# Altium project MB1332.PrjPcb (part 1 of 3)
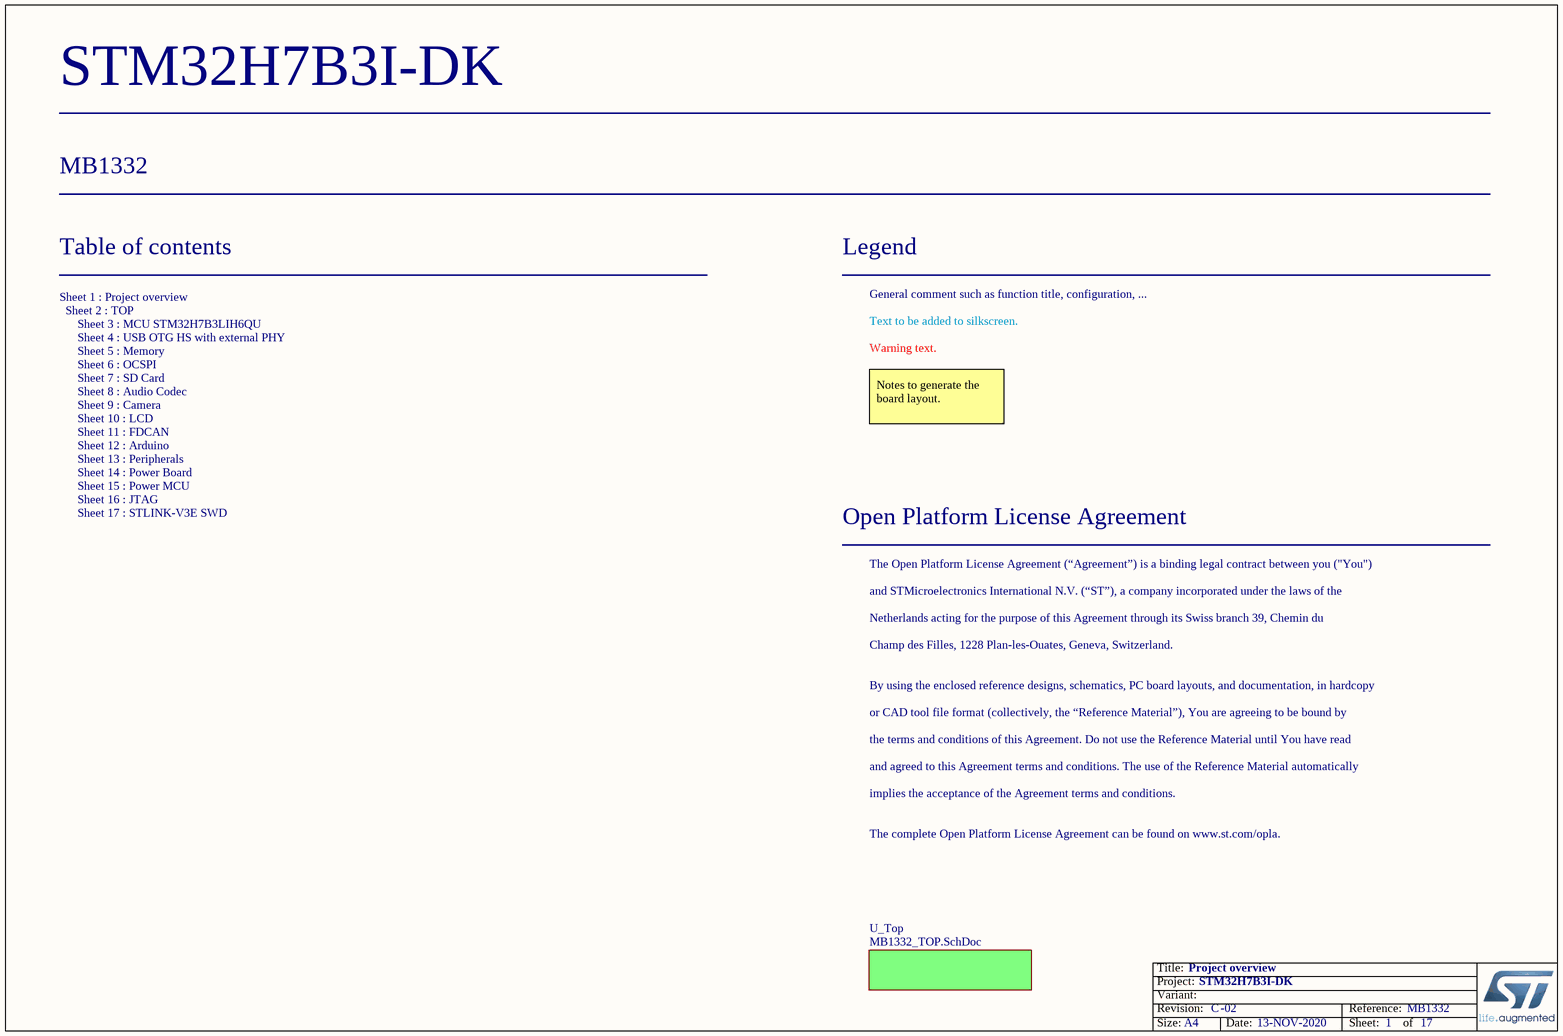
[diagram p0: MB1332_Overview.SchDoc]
Board_Reference: MB1332; Board_PCB_Revision: C; Board_Name: STM32H7B3I-DK; Board_Document_Date: 13-NOV-2020; Board_Assembly_Revision: 02
17 sheets, 382 parts. Net scope: flat (ports and power ports of the same name join across sheets).
Board file: MB1332.PcbDoc
Sheets:
  MB1332_Overview.SchDoc
    U_Top = MB1332_TOP.SchDoc
      U_Audio_Codec = Audio_Codec.SchDoc
      U_Camera = Camera.SchDoc
      U_FDCAN = FDCAN.SchDoc
      U_LCD = LCD.SchDoc
      U_Memory = Memory.SchDoc
      U_OCSPI = OCSPI.SchDoc
      U_Peripherals = Peripherals.SchDoc
      U_SDcard = SDcard.SchDoc
      U_USB_OTG_HS_externalPHY = USB_OTG_HS_externalPHY.SchDoc
      U_MCU = MCU.SchDoc
      U_Arduino = Arduino.SchDoc
      U_JTAG = JTAG.SchDoc
      U_STLink_V3E_SWD = STLink_V3E_SWD.SchDoc
      U_Power_Board = Power_Board.SchDoc
      U_Power_MCU = Power_MCU.SchDoc

## Sheet MB1332_Overview.SchDoc: Project overview
size A4; Date: Not used; ApprovedBy: Not used; CheckedBy: Not used; Author: Not used; CompanyName: STMicroelectronics; DrawnBy: Not used; Engineer: Not used; Organization: Not used; Address1: Not used; Address2: Not used; Address3: Not used; Address4: Not used; DocumentNumber: Not used; Revision: Not used; SheetNumber: 1; SheetTotal: 17

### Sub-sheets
U_Top = MB1332_TOP.SchDoc: no entries

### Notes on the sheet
- Table of contents
- Legend
- General comment such as function title, configuration, ...
- Text to be added to silkscreen.
- Warning text.
- Notes to generate the board layout.
- Sheet 1 : Project overview
  Sheet 2 : TOP
  Sheet 3 : MCU STM32H7B3LIH6QU
  Sheet 4 : USB OTG HS with external PHY
  Sheet 5 : Memory
  Sheet 6 : OCSPI
  Sheet 7 : SD Card
  Sheet 8 : Audio Codec
  Sheet 9 : Camera
  Sheet 10 : LCD
  Sheet 11 : FDCAN
  Sheet 12 : Arduino
  Sheet 13 : Peripherals
  Sheet 14 : Power Board
  Sheet 15 : Power MCU
  Sheet 16 : JTAG
  Sheet 17 : STLINK-V3E SWD
- Open Platform License Agreement
- The Open Platform License Agreement (“Agreement”) is a binding legal contract between you ("You")
- and STMicroelectronics International N.V. (“ST”), a company incorporated under the laws of the
- Netherlands acting for the purpose of this Agreement through its Swiss branch 39, Chemin du
- Champ des Filles, 1228 Plan-les-Ouates, Geneva, Switzerland.
- By using the enclosed reference designs, schematics, PC board layouts, and documentation, in hardcopy
- or CAD tool file format (collectively, the “Reference Material”), You are agreeing to be bound by
- the terms and conditions of this Agreement. Do not use the Reference Material until You have read
- and agreed to this Agreement terms and conditions. The use of the Reference Material automatically
- implies the acceptance of the Agreement terms and conditions.
- The complete Open Platform License Agreement can be found on www.st.com/opla.

## Sheet MB1332_TOP.SchDoc: TOP
size A3; Date: Not used; ApprovedBy: Not used; CheckedBy: Not used; Author: Not used; CompanyName: STMicroelectronics; DrawnBy: Not used; Engineer: Not used; Organization: Not used; Address1: Not used; Address2: Not used; Address3: Not used; Address4: Not used; DocumentNumber: Not used; Revision: Not used; SheetNumber: 2; SheetTotal: 17
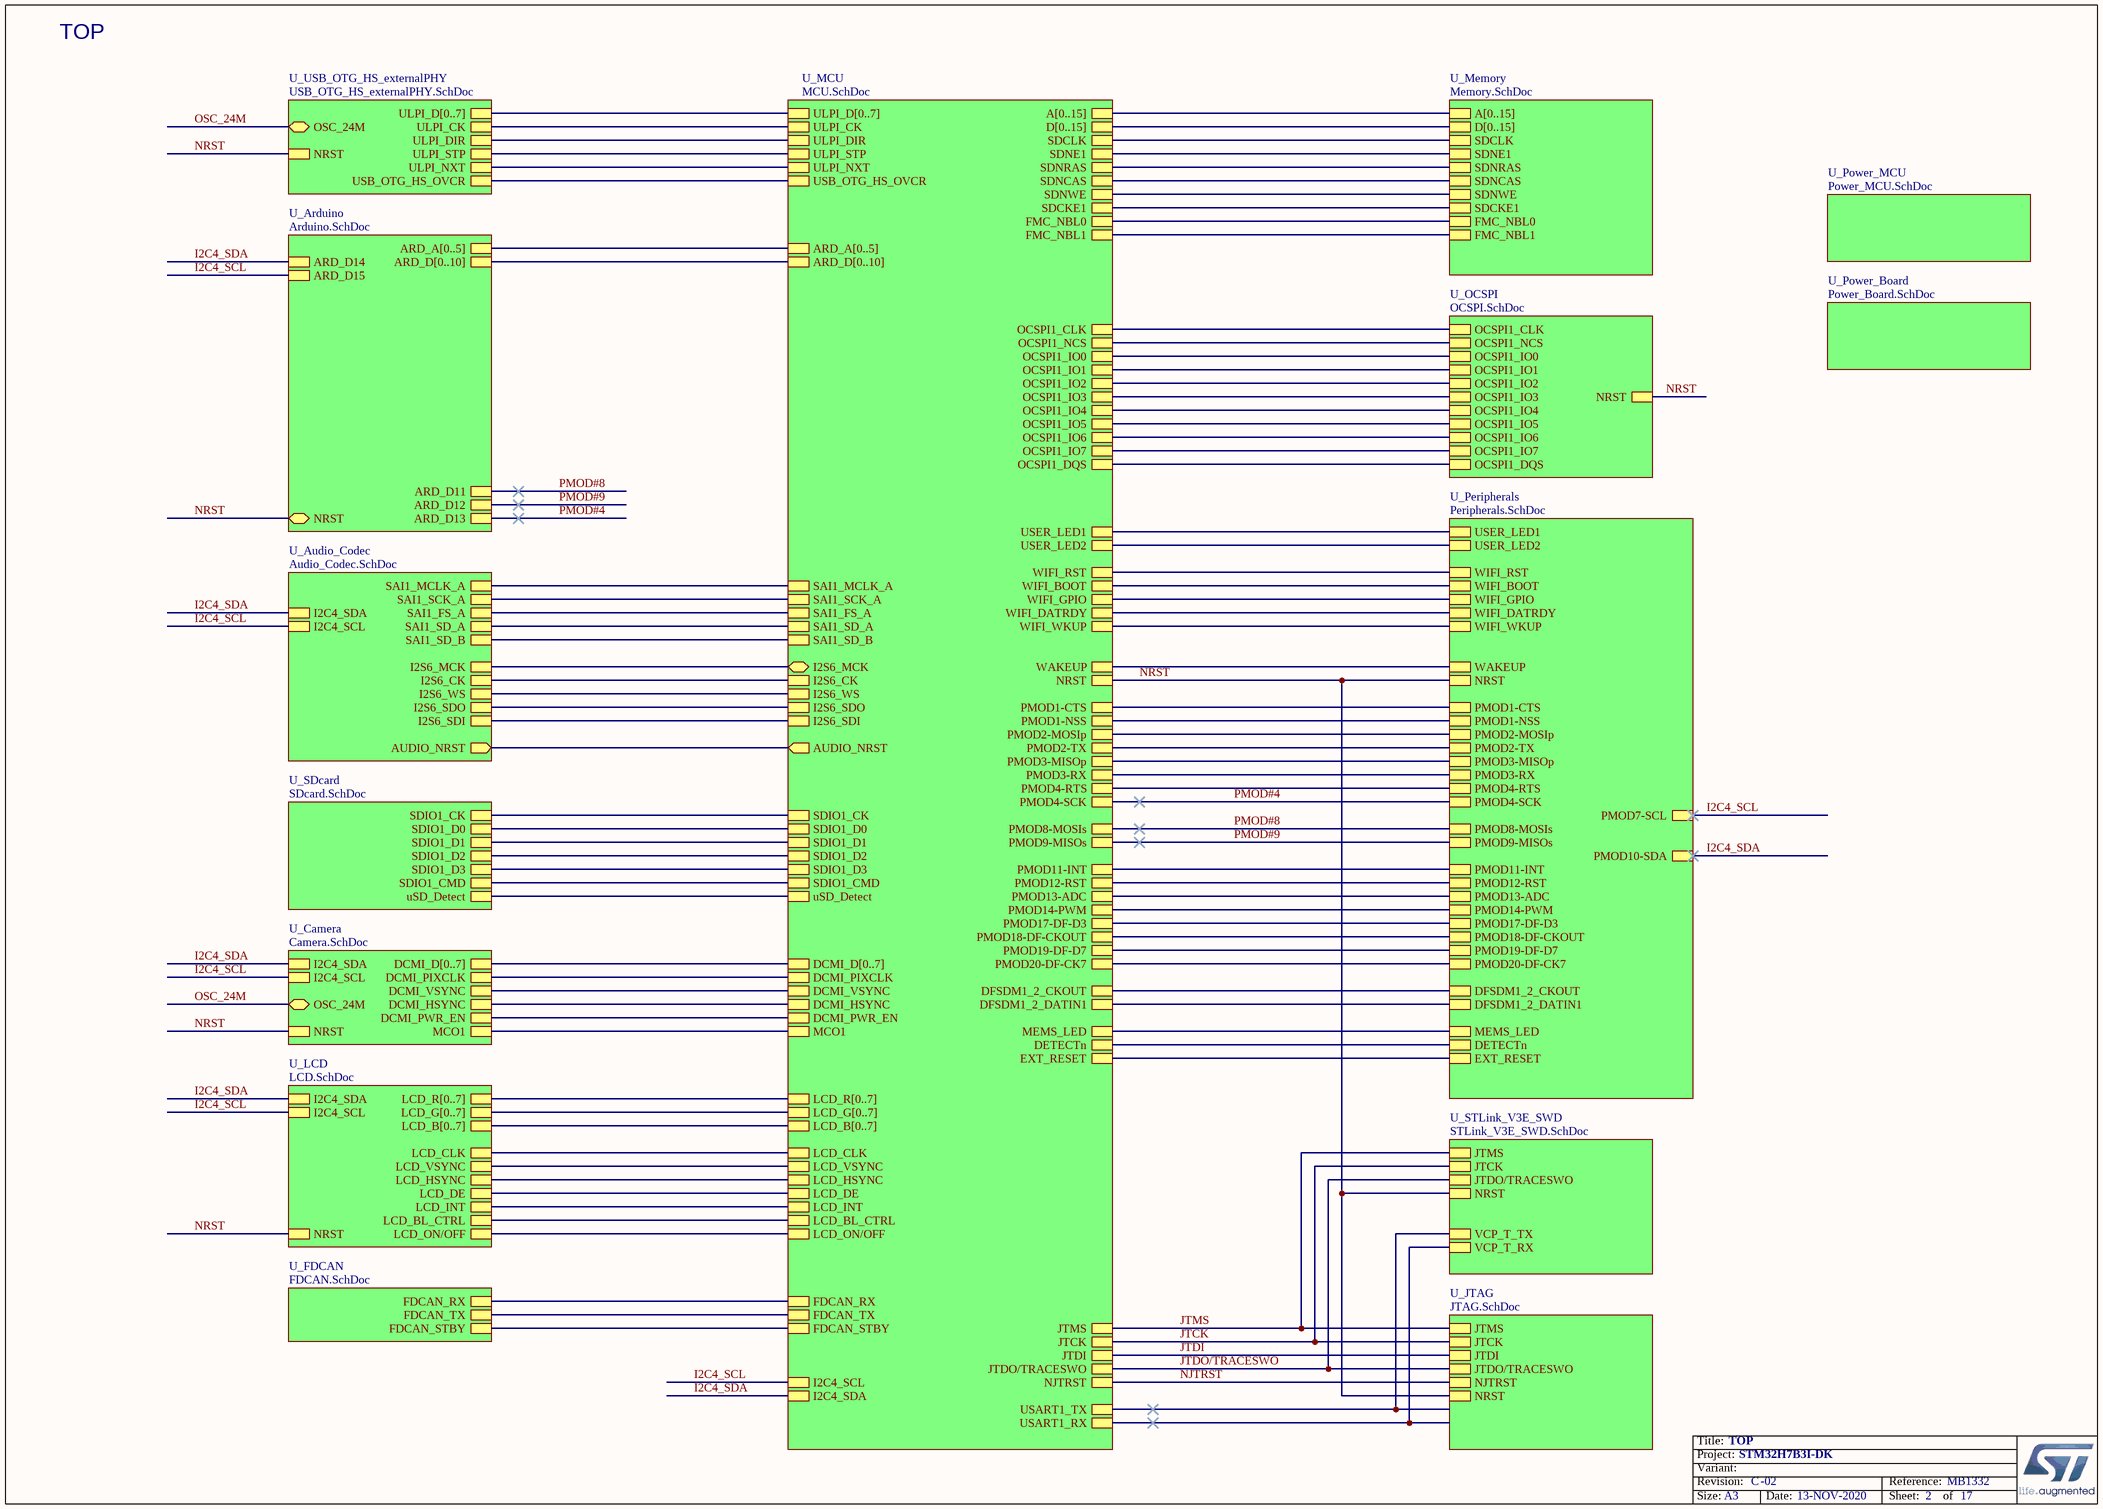
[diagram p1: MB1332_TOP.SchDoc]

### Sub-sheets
U_Arduino = Arduino.SchDoc: ARD_D13, ARD_D12, ARD_D11, ARD_D15, ARD_D14, ARD_A[0..5], ARD_D[0..10], NRST (bidir)
U_Audio_Codec = Audio_Codec.SchDoc: SAI1_MCLK_A, SAI1_SCK_A, SAI1_FS_A, SAI1_SD_A, SAI1_SD_B, I2C4_SCL, I2C4_SDA, I2S6_MCK, I2S6_CK, I2S6_WS, I2S6_SDO, I2S6_SDI, AUDIO_NRST (out)
U_Camera = Camera.SchDoc: NRST, DCMI_D[0..7], DCMI_PWR_EN, DCMI_VSYNC, DCMI_PIXCLK, I2C4_SDA, I2C4_SCL, DCMI_HSYNC, MCO1, OSC_24M
U_FDCAN = FDCAN.SchDoc: FDCAN_STBY, FDCAN_RX, FDCAN_TX
U_JTAG = JTAG.SchDoc: JTMS, JTCK, JTDI, JTDO/TRACESWO, NJTRST, NRST
U_LCD = LCD.SchDoc: LCD_R[0..7], I2C4_SDA, I2C4_SCL, LCD_B[0..7], LCD_G[0..7], NRST, LCD_HSYNC, LCD_VSYNC, LCD_CLK, LCD_DE, LCD_INT, LCD_BL_CTRL, LCD_ON/OFF
U_MCU = MCU.SchDoc: OCSPI1_NCS, SAI1_MCLK_A, SDNCAS, SDNE1, SDCKE1, NRST, LCD_HSYNC, LCD_VSYNC, LCD_CLK, MCO1, OCSPI1_CLK, OCSPI1_DQS, SDIO1_D0, SDIO1_D1, SDIO1_D2, SDIO1_D3, SDIO1_CK, WAKEUP, SDIO1_CMD, FMC_NBL0, FMC_NBL1, SDNRAS, LCD_G[0..7], LCD_B[0..7], D[0..15], A[0..15], ULPI_D[0..7], LCD_R[0..7], LCD_DE, ULPI_STP, ULPI_CK, LCD_INT, uSD_Detect, LCD_BL_CTRL, SAI1_SD_B, SAI1_FS_A, SAI1_SCK_A, SAI1_SD_A, JTMS, JTCK, JTDI, JTDO/TRACESWO, NJTRST, DCMI_HSYNC, DCMI_D[0..7], DCMI_PIXCLK, OCSPI1_IO1, OCSPI1_IO2, OCSPI1_IO3, OCSPI1_IO4, OCSPI1_IO7, OCSPI1_IO6, OCSPI1_IO5, ULPI_DIR, ULPI_NXT, SDNWE, DCMI_VSYNC, DCMI_PWR_EN, I2C4_SDA, I2C4_SCL, I2S6_SDO, I2S6_SDI, I2S6_CK, SDCLK, USB_OTG_HS_OVCR, USART1_TX, USART1_RX, OCSPI1_IO0, LCD_ON/OFF, FDCAN_RX, FDCAN_TX, FDCAN_STBY, MEMS_LED, EXT_RESET, DFSDM1_2_CKOUT, DFSDM1_2_DATIN1, I2S6_WS, WIFI_RST, ARD_A[0..5], ARD_D[0..10], USER_LED2, USER_LED1, AUDIO_NRST (out), PMOD13-ADC, PMOD12-RST, PMOD4-SCK, PMOD20-DF-CK7, PMOD8-MOSIs, PMOD2-MOSIp, PMOD3-RX, PMOD1-NSS, PMOD1-CTS, PMOD2-TX, PMOD11-INT, PMOD4-RTS, PMOD14-PWM, PMOD18-DF-CKOUT, PMOD9-MISOs, PMOD17-DF-D3, PMOD19-DF-D7, PMOD3-MISOp, WIFI_BOOT, I2S6_MCK (bidir), WIFI_WKUP, WIFI_GPIO, WIFI_DATRDY, DETECTn
U_Memory = Memory.SchDoc: FMC_NBL0, FMC_NBL1, D[0..15], A[0..15], SDNCAS, SDNWE, SDNRAS, SDNE1, SDCKE1, SDCLK
U_OCSPI = OCSPI.SchDoc: NRST, OCSPI1_IO0, OCSPI1_IO1, OCSPI1_IO2, OCSPI1_IO3, OCSPI1_IO4, OCSPI1_IO5, OCSPI1_IO6, OCSPI1_IO7, OCSPI1_DQS, OCSPI1_CLK, OCSPI1_NCS
U_Peripherals = Peripherals.SchDoc: WIFI_RST, WAKEUP, NRST, DFSDM1_2_CKOUT, DFSDM1_2_DATIN1, MEMS_LED, EXT_RESET, USER_LED2, USER_LED1, PMOD4-RTS, PMOD2-MOSIp, PMOD3-MISOp, PMOD1-CTS, PMOD2-TX, PMOD8-MOSIs, PMOD9-MISOs, PMOD3-RX, PMOD4-SCK, PMOD7-SCL, PMOD10-SDA, PMOD11-INT, PMOD12-RST, PMOD17-DF-D3, PMOD18-DF-CKOUT, PMOD19-DF-D7, PMOD13-ADC, PMOD14-PWM, PMOD20-DF-CK7, PMOD1-NSS, WIFI_BOOT, WIFI_WKUP, WIFI_GPIO, WIFI_DATRDY, DETECTn
U_Power_Board = Power_Board.SchDoc: no entries
U_Power_MCU = Power_MCU.SchDoc: no entries
U_SDcard = SDcard.SchDoc: SDIO1_D0, SDIO1_D1, SDIO1_D2, SDIO1_D3, SDIO1_CMD, SDIO1_CK, uSD_Detect
U_STLink_V3E_SWD = STLink_V3E_SWD.SchDoc: JTCK, JTDO/TRACESWO, NRST, JTMS, VCP_T_TX, VCP_T_RX
U_USB_OTG_HS_externalPHY = USB_OTG_HS_externalPHY.SchDoc: ULPI_D[0..7], ULPI_CK, ULPI_DIR, ULPI_NXT, ULPI_STP, NRST, USB_OTG_HS_OVCR, OSC_24M

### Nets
I2C4_SCL: sheet U_Audio_Codec/I2C4_SCL, sheet U_Camera/I2C4_SCL, sheet U_LCD/I2C4_SCL, sheet U_Peripherals/PMOD7-SCL, sheet U_MCU/I2C4_SCL, sheet U_Arduino/ARD_D15
I2C4_SDA: sheet U_Audio_Codec/I2C4_SDA, sheet U_Camera/I2C4_SDA, sheet U_LCD/I2C4_SDA, sheet U_Peripherals/PMOD10-SDA, sheet U_MCU/I2C4_SDA, sheet U_Arduino/ARD_D14
JTCK: sheet U_MCU/JTCK, sheet U_JTAG/JTCK, sheet U_STLink_V3E_SWD/JTCK
JTDI: sheet U_MCU/JTDI, sheet U_JTAG/JTDI
JTDO/TRACESWO: sheet U_MCU/JTDO/TRACESWO, sheet U_JTAG/JTDO/TRACESWO, sheet U_STLink_V3E_SWD/JTDO/TRACESWO
JTMS: sheet U_MCU/JTMS, sheet U_JTAG/JTMS, sheet U_STLink_V3E_SWD/JTMS
NJTRST: sheet U_MCU/NJTRST, sheet U_JTAG/NJTRST
NRST: sheet U_Camera/NRST, sheet U_LCD/NRST, sheet U_OCSPI/NRST, sheet U_Peripherals/NRST, sheet U_USB_OTG_HS_externalPHY/NRST, sheet U_MCU/NRST, sheet U_Arduino/NRST, sheet U_JTAG/NRST, sheet U_STLink_V3E_SWD/NRST
OSC_24M: sheet U_Camera/OSC_24M, sheet U_USB_OTG_HS_externalPHY/OSC_24M
PMOD#4: sheet U_Peripherals/PMOD4-SCK, sheet U_MCU/PMOD4-SCK, sheet U_Arduino/ARD_D13
PMOD#8: sheet U_Peripherals/PMOD8-MOSIs, sheet U_MCU/PMOD8-MOSIs, sheet U_Arduino/ARD_D11
PMOD#9: sheet U_Peripherals/PMOD9-MISOs, sheet U_MCU/PMOD9-MISOs, sheet U_Arduino/ARD_D12
(unnamed): sheet U_Audio_Codec/SAI1_MCLK_A, sheet U_MCU/SAI1_MCLK_A
(unnamed): sheet U_Audio_Codec/SAI1_SCK_A, sheet U_MCU/SAI1_SCK_A  [a separate net that carries the same name]
(unnamed): sheet U_Audio_Codec/SAI1_FS_A, sheet U_MCU/SAI1_FS_A  [a separate net that carries the same name]
(unnamed): sheet U_Audio_Codec/SAI1_SD_A, sheet U_MCU/SAI1_SD_A  [a separate net that carries the same name]
(unnamed): sheet U_Audio_Codec/SAI1_SD_B, sheet U_MCU/SAI1_SD_B  [a separate net that carries the same name]
(unnamed): sheet U_Audio_Codec/I2S6_MCK, sheet U_MCU/I2S6_MCK  [a separate net that carries the same name]
(unnamed): sheet U_Audio_Codec/I2S6_CK, sheet U_MCU/I2S6_CK  [a separate net that carries the same name]
(unnamed): sheet U_Audio_Codec/I2S6_WS, sheet U_MCU/I2S6_WS  [a separate net that carries the same name]
(unnamed): sheet U_Audio_Codec/I2S6_SDO, sheet U_MCU/I2S6_SDO  [a separate net that carries the same name]
(unnamed): sheet U_Audio_Codec/I2S6_SDI, sheet U_MCU/I2S6_SDI  [a separate net that carries the same name]
(unnamed): sheet U_Audio_Codec/AUDIO_NRST, sheet U_MCU/AUDIO_NRST  [a separate net that carries the same name]
(unnamed): sheet U_Camera/DCMI_PWR_EN, sheet U_MCU/DCMI_PWR_EN  [a separate net that carries the same name]
(unnamed): sheet U_Camera/DCMI_VSYNC, sheet U_MCU/DCMI_VSYNC  [a separate net that carries the same name]
(unnamed): sheet U_Camera/DCMI_PIXCLK, sheet U_MCU/DCMI_PIXCLK  [a separate net that carries the same name]
(unnamed): sheet U_Camera/DCMI_HSYNC, sheet U_MCU/DCMI_HSYNC  [a separate net that carries the same name]
(unnamed): sheet U_Camera/MCO1, sheet U_MCU/MCO1  [a separate net that carries the same name]
(unnamed): sheet U_FDCAN/FDCAN_STBY, sheet U_MCU/FDCAN_STBY  [a separate net that carries the same name]
(unnamed): sheet U_FDCAN/FDCAN_RX, sheet U_MCU/FDCAN_RX  [a separate net that carries the same name]
(unnamed): sheet U_FDCAN/FDCAN_TX, sheet U_MCU/FDCAN_TX  [a separate net that carries the same name]
(unnamed): sheet U_LCD/LCD_HSYNC, sheet U_MCU/LCD_HSYNC  [a separate net that carries the same name]
(unnamed): sheet U_LCD/LCD_VSYNC, sheet U_MCU/LCD_VSYNC  [a separate net that carries the same name]
(unnamed): sheet U_LCD/LCD_CLK, sheet U_MCU/LCD_CLK  [a separate net that carries the same name]
(unnamed): sheet U_LCD/LCD_DE, sheet U_MCU/LCD_DE  [a separate net that carries the same name]
(unnamed): sheet U_LCD/LCD_INT, sheet U_MCU/LCD_INT  [a separate net that carries the same name]
(unnamed): sheet U_LCD/LCD_BL_CTRL, sheet U_MCU/LCD_BL_CTRL  [a separate net that carries the same name]
(unnamed): sheet U_LCD/LCD_ON/OFF, sheet U_MCU/LCD_ON/OFF  [a separate net that carries the same name]
(unnamed): sheet U_Memory/FMC_NBL0, sheet U_MCU/FMC_NBL0  [a separate net that carries the same name]
(unnamed): sheet U_Memory/FMC_NBL1, sheet U_MCU/FMC_NBL1  [a separate net that carries the same name]
(unnamed): sheet U_Memory/SDNCAS, sheet U_MCU/SDNCAS  [a separate net that carries the same name]
(unnamed): sheet U_Memory/SDNWE, sheet U_MCU/SDNWE  [a separate net that carries the same name]
(unnamed): sheet U_Memory/SDNRAS, sheet U_MCU/SDNRAS  [a separate net that carries the same name]
(unnamed): sheet U_Memory/SDNE1, sheet U_MCU/SDNE1  [a separate net that carries the same name]
(unnamed): sheet U_Memory/SDCKE1, sheet U_MCU/SDCKE1  [a separate net that carries the same name]
(unnamed): sheet U_Memory/SDCLK, sheet U_MCU/SDCLK  [a separate net that carries the same name]
(unnamed): sheet U_OCSPI/OCSPI1_IO0, sheet U_MCU/OCSPI1_IO0  [a separate net that carries the same name]
(unnamed): sheet U_OCSPI/OCSPI1_IO1, sheet U_MCU/OCSPI1_IO1  [a separate net that carries the same name]
(unnamed): sheet U_OCSPI/OCSPI1_IO2, sheet U_MCU/OCSPI1_IO2  [a separate net that carries the same name]
(unnamed): sheet U_OCSPI/OCSPI1_IO3, sheet U_MCU/OCSPI1_IO3  [a separate net that carries the same name]
(unnamed): sheet U_OCSPI/OCSPI1_IO4, sheet U_MCU/OCSPI1_IO4  [a separate net that carries the same name]
(unnamed): sheet U_OCSPI/OCSPI1_IO5, sheet U_MCU/OCSPI1_IO5  [a separate net that carries the same name]
(unnamed): sheet U_OCSPI/OCSPI1_IO6, sheet U_MCU/OCSPI1_IO6  [a separate net that carries the same name]
(unnamed): sheet U_OCSPI/OCSPI1_IO7, sheet U_MCU/OCSPI1_IO7  [a separate net that carries the same name]
(unnamed): sheet U_OCSPI/OCSPI1_DQS, sheet U_MCU/OCSPI1_DQS  [a separate net that carries the same name]
(unnamed): sheet U_OCSPI/OCSPI1_CLK, sheet U_MCU/OCSPI1_CLK  [a separate net that carries the same name]
(unnamed): sheet U_OCSPI/OCSPI1_NCS, sheet U_MCU/OCSPI1_NCS  [a separate net that carries the same name]
(unnamed): sheet U_Peripherals/WIFI_RST, sheet U_MCU/WIFI_RST  [a separate net that carries the same name]
(unnamed): sheet U_Peripherals/WAKEUP, sheet U_MCU/WAKEUP  [a separate net that carries the same name]
(unnamed): sheet U_Peripherals/DFSDM1_2_CKOUT, sheet U_MCU/DFSDM1_2_CKOUT  [a separate net that carries the same name]
(unnamed): sheet U_Peripherals/DFSDM1_2_DATIN1, sheet U_MCU/DFSDM1_2_DATIN1  [a separate net that carries the same name]
(unnamed): sheet U_Peripherals/MEMS_LED, sheet U_MCU/MEMS_LED  [a separate net that carries the same name]
(unnamed): sheet U_Peripherals/EXT_RESET, sheet U_MCU/EXT_RESET  [a separate net that carries the same name]
(unnamed): sheet U_Peripherals/USER_LED2, sheet U_MCU/USER_LED2  [a separate net that carries the same name]
(unnamed): sheet U_Peripherals/USER_LED1, sheet U_MCU/USER_LED1  [a separate net that carries the same name]
(unnamed): sheet U_Peripherals/PMOD4-RTS, sheet U_MCU/PMOD4-RTS  [a separate net that carries the same name]
(unnamed): sheet U_Peripherals/PMOD2-MOSIp, sheet U_MCU/PMOD2-MOSIp  [a separate net that carries the same name]
(unnamed): sheet U_Peripherals/PMOD3-MISOp, sheet U_MCU/PMOD3-MISOp  [a separate net that carries the same name]
(unnamed): sheet U_Peripherals/PMOD1-CTS, sheet U_MCU/PMOD1-CTS  [a separate net that carries the same name]
(unnamed): sheet U_Peripherals/PMOD2-TX, sheet U_MCU/PMOD2-TX  [a separate net that carries the same name]
(unnamed): sheet U_Peripherals/PMOD3-RX, sheet U_MCU/PMOD3-RX  [a separate net that carries the same name]
(unnamed): sheet U_Peripherals/PMOD11-INT, sheet U_MCU/PMOD11-INT  [a separate net that carries the same name]
(unnamed): sheet U_Peripherals/PMOD12-RST, sheet U_MCU/PMOD12-RST  [a separate net that carries the same name]
(unnamed): sheet U_Peripherals/PMOD17-DF-D3, sheet U_MCU/PMOD17-DF-D3  [a separate net that carries the same name]
(unnamed): sheet U_Peripherals/PMOD18-DF-CKOUT, sheet U_MCU/PMOD18-DF-CKOUT  [a separate net that carries the same name]
(unnamed): sheet U_Peripherals/PMOD19-DF-D7, sheet U_MCU/PMOD19-DF-D7  [a separate net that carries the same name]
(unnamed): sheet U_Peripherals/PMOD13-ADC, sheet U_MCU/PMOD13-ADC  [a separate net that carries the same name]
(unnamed): sheet U_Peripherals/PMOD14-PWM, sheet U_MCU/PMOD14-PWM  [a separate net that carries the same name]
(unnamed): sheet U_Peripherals/PMOD20-DF-CK7, sheet U_MCU/PMOD20-DF-CK7  [a separate net that carries the same name]
(unnamed): sheet U_Peripherals/PMOD1-NSS, sheet U_MCU/PMOD1-NSS  [a separate net that carries the same name]
(unnamed): sheet U_Peripherals/WIFI_BOOT, sheet U_MCU/WIFI_BOOT  [a separate net that carries the same name]
(unnamed): sheet U_Peripherals/WIFI_WKUP, sheet U_MCU/WIFI_WKUP  [a separate net that carries the same name]
(unnamed): sheet U_Peripherals/WIFI_GPIO, sheet U_MCU/WIFI_GPIO  [a separate net that carries the same name]
(unnamed): sheet U_Peripherals/WIFI_DATRDY, sheet U_MCU/WIFI_DATRDY  [a separate net that carries the same name]
(unnamed): sheet U_Peripherals/DETECTn, sheet U_MCU/DETECTn  [a separate net that carries the same name]
(unnamed): sheet U_SDcard/SDIO1_D0, sheet U_MCU/SDIO1_D0  [a separate net that carries the same name]
(unnamed): sheet U_SDcard/SDIO1_D1, sheet U_MCU/SDIO1_D1  [a separate net that carries the same name]
(unnamed): sheet U_SDcard/SDIO1_D2, sheet U_MCU/SDIO1_D2  [a separate net that carries the same name]
(unnamed): sheet U_SDcard/SDIO1_D3, sheet U_MCU/SDIO1_D3  [a separate net that carries the same name]
(unnamed): sheet U_SDcard/SDIO1_CMD, sheet U_MCU/SDIO1_CMD  [a separate net that carries the same name]
(unnamed): sheet U_SDcard/SDIO1_CK, sheet U_MCU/SDIO1_CK  [a separate net that carries the same name]
(unnamed): sheet U_SDcard/uSD_Detect, sheet U_MCU/uSD_Detect  [a separate net that carries the same name]
(unnamed): sheet U_USB_OTG_HS_externalPHY/ULPI_CK, sheet U_MCU/ULPI_CK  [a separate net that carries the same name]
(unnamed): sheet U_USB_OTG_HS_externalPHY/ULPI_DIR, sheet U_MCU/ULPI_DIR  [a separate net that carries the same name]
(unnamed): sheet U_USB_OTG_HS_externalPHY/ULPI_NXT, sheet U_MCU/ULPI_NXT  [a separate net that carries the same name]
(unnamed): sheet U_USB_OTG_HS_externalPHY/ULPI_STP, sheet U_MCU/ULPI_STP  [a separate net that carries the same name]
(unnamed): sheet U_USB_OTG_HS_externalPHY/USB_OTG_HS_OVCR, sheet U_MCU/USB_OTG_HS_OVCR  [a separate net that carries the same name]
(unnamed): sheet U_MCU/USART1_TX, sheet U_STLink_V3E_SWD/VCP_T_TX  [a separate net that carries the same name]
(unnamed): sheet U_MCU/USART1_RX, sheet U_STLink_V3E_SWD/VCP_T_RX  [a separate net that carries the same name]

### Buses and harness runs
bus sheet U_Arduino/ARD_A[0..5] = sheet U_MCU/ARD_A[0..5]
bus sheet U_Arduino/ARD_D[0..10] = sheet U_MCU/ARD_D[0..10]
bus sheet U_Camera/DCMI_D[0..7] = sheet U_MCU/DCMI_D[0..7]
bus sheet U_LCD/LCD_B[0..7] = sheet U_MCU/LCD_B[0..7]
bus sheet U_LCD/LCD_G[0..7] = sheet U_MCU/LCD_G[0..7]
bus sheet U_LCD/LCD_R[0..7] = sheet U_MCU/LCD_R[0..7]
bus sheet U_MCU/A[0..15] = sheet U_Memory/A[0..15]
bus sheet U_MCU/D[0..15] = sheet U_Memory/D[0..15]
bus sheet U_MCU/ULPI_D[0..7] = sheet U_USB_OTG_HS_externalPHY/ULPI_D[0..7]

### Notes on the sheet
- TOP

## Sheet Audio_Codec.SchDoc: Audio Codec
size A4; Date: Not used; ApprovedBy: Not used; CheckedBy: Not used; Author: Not used; CompanyName: STMicroelectronics; DrawnBy: Not used; Engineer: Not used; Organization: Not used; Address1: Not used; Address2: Not used; Address3: Not used; Address4: Not used; DocumentNumber: Not used; Revision: Not used; SheetNumber: 8; SheetTotal: 17
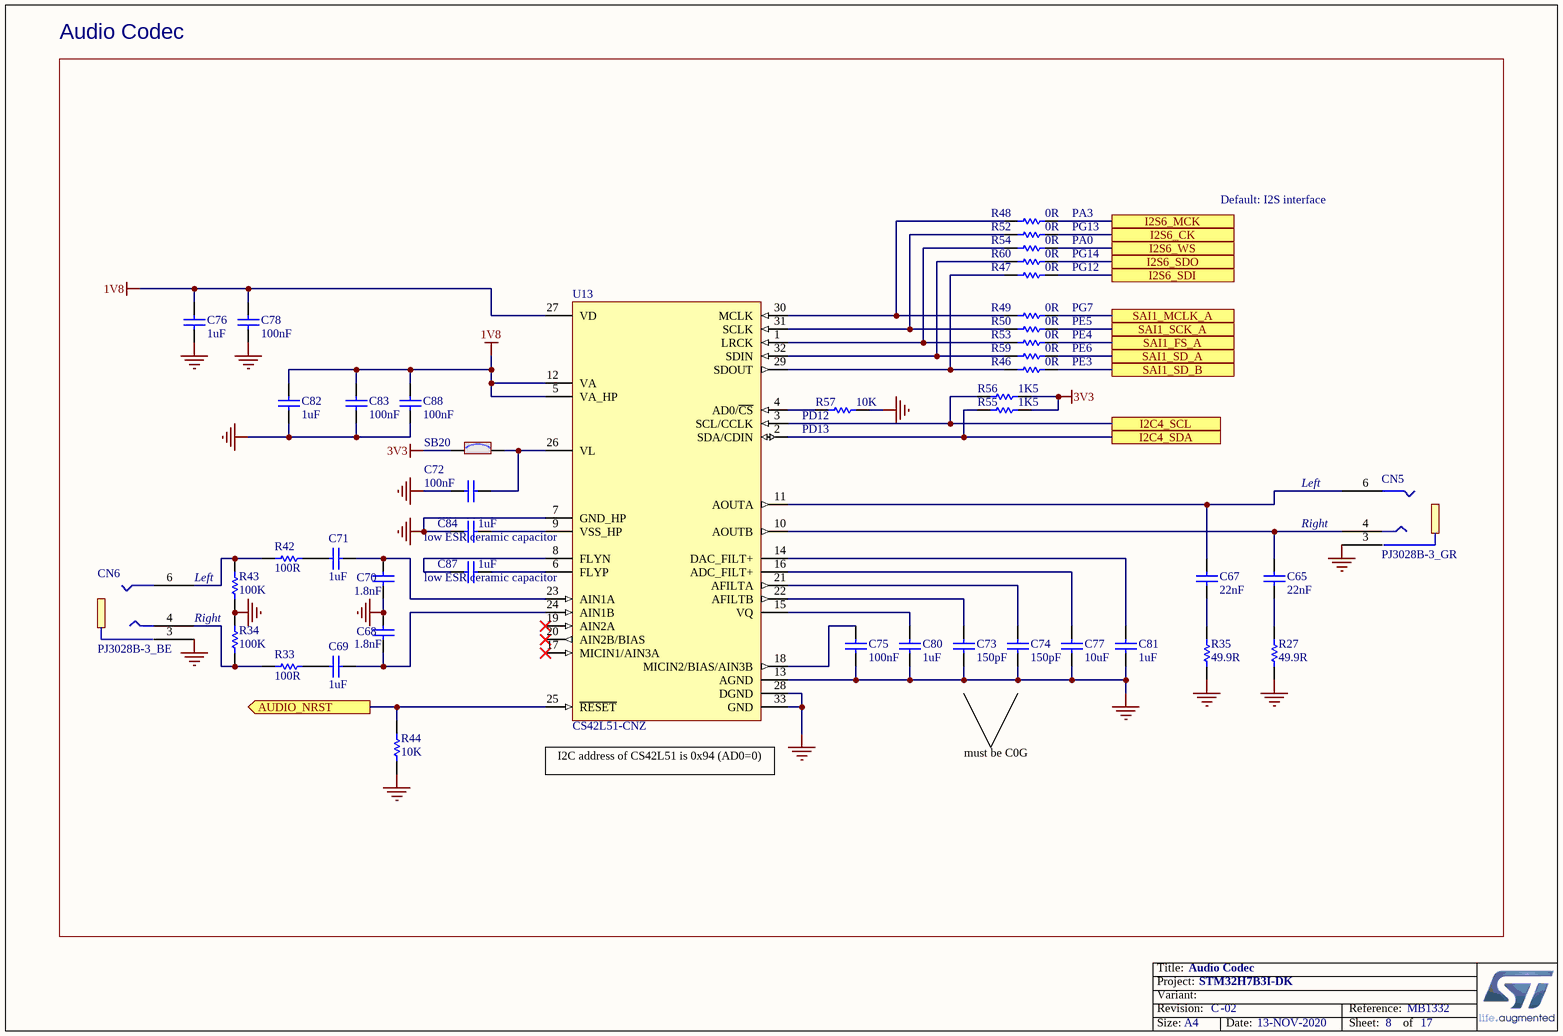
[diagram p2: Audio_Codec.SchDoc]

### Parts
C65  value 22nF  [C0603]  (hidden comment: Capacitor)
C67  value 22nF  [C0603]  (hidden comment: Capacitor)
C68  value 1.8nF  [C0402]  (hidden comment: Capacitor)
C69  value 1uF  [C0402]  (hidden comment: Capacitor)
C70  value 1.8nF  [C0402]  (hidden comment: Capacitor)
C71  value 1uF  [C0402]  (hidden comment: Capacitor)
C72  value 100nF  [C0402]  (hidden comment: Capacitor)
C73  value 150pF  [C0402]  (hidden comment: Capacitor)
C74  value 150pF  [C0402]  (hidden comment: Capacitor)
C75  value 100nF  [C0402]  (hidden comment: Capacitor)
C76  value 1uF  [C0402]  (hidden comment: Capacitor)
C77  value 10uF  [C0603]  (hidden comment: Capacitor)
C78  value 100nF  [C0402]  (hidden comment: Capacitor)
C80  value 1uF  [C0402]  (hidden comment: Capacitor)
C81  value 1uF  [C0402]  (hidden comment: Capacitor)
C82  value 1uF  [C0402]  (hidden comment: Capacitor)
C83  value 100nF  [C0402]  (hidden comment: Capacitor)
C84  value 1uF  [C0402]  (hidden comment: Capacitor)
C87  value 1uF  [C0402]  (hidden comment: Capacitor)
C88  value 100nF  [C0402]  (hidden comment: Capacitor)
CN5  value PJ3028B-3_GR  [CON_PHONE-JACK-3P5_HY_PJ3028B]  (hidden comment: Jack_PJ3028B-3_3P)
CN6  value PJ3028B-3_BE  [CON_PHONE-JACK-3P5_HY_PJ3028B]  (hidden comment: Jack_PJ3028B-3_3P)
R27  value 49.9R  [R0603]  (hidden comment: Resistor)
R33  value 100R  [R0402]  (hidden comment: Resistor)
R34  value 100K  [R0402]  (hidden comment: Resistor)
R35  value 49.9R  [R0603]  (hidden comment: Resistor)
R42  value 100R  [R0402]  (hidden comment: Resistor)
R43  value 100K  [R0402]  (hidden comment: Resistor)
R44  value 10K  [R0402]  (hidden comment: Resistor)
R46  value 0R  [R0402]  (hidden comment: Resistor)
R47  value 0R  [R0402]  (hidden comment: Resistor)
R48  value 0R  [R0402]  (hidden comment: Resistor)
R49  value 0R  [R0402]  (hidden comment: Resistor)
R50  value 0R  [R0402]  (hidden comment: Resistor)
R52  value 0R  [R0402]  (hidden comment: Resistor)
R53  value 0R  [R0402]  (hidden comment: Resistor)
R54  value 0R  [R0402]  (hidden comment: Resistor)
R55  value 1K5  [R0402]  (hidden comment: Resistor)
R56  value 1K5  [R0402]  (hidden comment: Resistor)
R57  value 10K  [R0402]  (hidden comment: Resistor)
R59  value 0R  [R0402]  (hidden comment: Resistor)
R60  value 0R  [R0402]  (hidden comment: Resistor)
SB20  SB_ON  [SOLDER-BRIDGE_R0603-0R]  (value not drawn)
U13  CS42L51-CNZ  [ICC_QFN32-EPAD_5X5_P050]

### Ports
AUDIO_NRST (out), I2C4_SCL, I2C4_SDA, I2S6_CK, I2S6_MCK, I2S6_SDI, I2S6_SDO, I2S6_WS, SAI1_FS_A, SAI1_MCLK_A, SAI1_SCK_A, SAI1_SD_A, SAI1_SD_B

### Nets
1V8: C76.2 C78.2 C82.1 C83.2 C88.2 U13.5(VA_HP) U13.12(VA) U13.27(VD)
3V3: R55.2 R56.2 SB20.1
GND: C68.2 C70.1 C72.2 C73.1 C74.1 C75.2 C76.1 C77.1 C78.1 C80.2 C81.2 C82.2 C83.1 C84.2 C88.1 CN5.3 CN6.3 R27.1 R34.2 R35.1 R43.1 R44.1 R57.2 U13.7(GND_HP) U13.13(AGND) U13.28(DGND) U13.33(GND)
AUDIO_NRST: R44.2 U13.25(~{RESET}) ; port AUDIO_NRST
I2C4_SCL: R56.1 U13.3(SCL/CCLK) ; port I2C4_SCL
I2C4_SDA: R55.1 U13.2(SDA/CDIN) ; port I2C4_SDA
I2S6_CK: R52.2 ; port I2S6_CK
I2S6_MCK: R48.2 ; port I2S6_MCK
I2S6_SDI: R47.2 ; port I2S6_SDI
I2S6_SDO: R60.2 ; port I2S6_SDO
I2S6_WS: R54.2 ; port I2S6_WS
SAI1_FS_A: R53.2 ; port SAI1_FS_A
SAI1_MCLK_A: R49.2 ; port SAI1_MCLK_A
SAI1_SCK_A: R50.2 ; port SAI1_SCK_A
SAI1_SD_A: R59.2 ; port SAI1_SD_A
SAI1_SD_B: R46.2 ; port SAI1_SD_B
NetC65_1: C65.1 CN5.4 U13.10(AOUTB)
NetC65_2: C65.2 R27.2
NetC67_1: C67.1 R35.2
NetC67_2: C67.2 CN5.6 U13.11(AOUTA)
NetC68_1: C68.1 C69.2 U13.24(AIN1B)
NetC69_1: C69.1 R33.2
NetC70_2: C70.2 C71.2 U13.23(AIN1A)
NetC71_1: C71.1 R42.2
NetC72_1: C72.1 SB20.2 U13.26(VL)
NetC73_2: C73.2 U13.22(AFILTB)
NetC74_2: C74.2 U13.21(AFILTA)
NetC75_1: C75.1 U13.18(MICIN2/BIAS/AIN3B)
NetC77_2: C77.2 U13.16(ADC_FILT+)
NetC80_1: C80.1 U13.15(VQ)
NetC81_1: C81.1 U13.14(DAC_FILT+)
NetC84_1: C84.1 U13.9(VSS_HP)
NetC87_1: C87.1 U13.6(FLYP)
NetC87_2: C87.2 U13.8(FLYN)
NetCN6_4: CN6.4 R33.1 R34.1
NetCN6_6: CN6.6 R42.1 R43.2
NetR46_1: R46.1 R47.1 U13.29(SDOUT)
NetR48_1: R48.1 R49.1 U13.30(MCLK)
NetR50_1: R50.1 R52.1 U13.31(SCLK)
NetR53_1: R53.1 R54.1 U13.1(LRCK)
NetR57_1: R57.1 U13.4(AD0/~{CS})
NetR59_1: R59.1 R60.1 U13.32(SDIN)

Not connected (* = marked no-connect by the designer): U13 17(MICIN1/AIN3A)* 19(AIN2A)* 20(AIN2B/BIAS)*

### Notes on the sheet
- Audio Codec
- PA0
- PA3
- PG13
- Default: I2S interface
- PG7
- PG14
- PG12
- PE5
- PE4
- PE6
- PE3
- (near R57) PD12
- (near R57) PD13
- Left
- (near R43) Left
- low ESR ceramic capacitor
- Right
- (near U13) I2C address of CS42L51 is 0x94 (AD0=0)
- must be C0G

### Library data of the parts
C65 C67 = MCD-00555: Capacitor, MLCC, 22nF, 10%, 25V, X7R, 0603, T=0,8mm; Manufacturer_Part_Number: CC0603KRX7R8BB223; Manufacturer: YAGEO; Provided_By: SUBCO
C68 C70 = MCD-00694: Capacitor, MLCC, 1.8nF, 50V, X7R, 10%, 0402, T=0.5mm; Manufacturer_Part_Number: CC0402KRX7R9BB182; Manufacturer: YAGEO; Provided_By: SUBCO
C69 C71 C76 C80-C82 C84 C87 = MCD-01722: Capacitor, 1uF, 10V, X5R, 10%, 0402, T=0.5mm; Manufacturer_Part_Number: CC0402KRX5R6BB105; Manufacturer: YAGEO; Provided_By: SUBCO
C72 C75 C78 C83 C88 = MCD-00102: Capacitor, MLCC, 100nF, 16V, X7R, 10%, 0402, T=0,5mm; Manufacturer_Part_Number: CC0402KRX7R7BB104; Manufacturer: YAGEO; Alternate_Manufacturer_Part_Number: GCM155R71C104KA55D; Alternate_Manufacturer: MURATA; Provided_By: SUBCO
C73 C74 = MCD-00672: Capacitor, MLCC, 150pF, 50V, NPO, 5%, 0402, T=0,5mm; Manufacturer_Part_Number: CC0402JRNPO9BN151; Manufacturer: YAGEO; Provided_By: SUBCO
C77 = MCD-00098: Capacitor, MLCC, 10uF, 6V3, X5R, 10%, 0603, T=0,8mm; Manufacturer_Part_Number: CC0603KRX5R5BB106; Manufacturer: YAGEO; Provided_By: SUBCO
CN5 = MCD-00018: Connector Jack socket Stereo 3.5mm, 3 pins, RA, SMT, Green (Line output); Manufacturer: QIAOD; Alternate_Manufacturer_Part_Number: PJ30280-3_GR; Provided_By: SUBCO
CN6 = MCD-00682: Connector Jack socket Stereo 3.5mm, 3 pins, RA, SMT, Blue (Line input); Manufacturer: QIAOD; Alternate_Manufacturer_Part_Number: PJ30280-3_BE; Provided_By: SUBCO
R27 R35 = MCD-00564: Resistor,49R9,0603,1%,1/10W; Manufacturer_Part_Number: RC0603FR-0749R9L; Manufacturer: YAGEO; Provided_By: SUBCO
R33 R42 = MCD-00119: Resistor,100R,0402,1%,1/16W; Manufacturer_Part_Number: RC0402FR-07100RL; Manufacturer: YAGEO; Provided_By: SUBCO
R34 R43 = MCD-00059: Resistor,100K,0402,1%,1/16W; Manufacturer_Part_Number: RC0402FR-07100KL; Manufacturer: YAGEO; Alternate_Manufacturer_Part_Number: RT0402FRE07100KL; Provided_By: SUBCO
R44 R57 = MCD-00053: Resistor,10K,0402,1%,1/16W; Manufacturer_Part_Number: RC0402FR-0710KL; Manufacturer: YAGEO; Provided_By: SUBCO
R46-R50 R52-R54 R59 R60 = MCD-00052: Resistor,0R,0402,5%,1/16W; Manufacturer_Part_Number: RC0402JR-070RL; Manufacturer: YAGEO; Provided_By: SUBCO
R55 R56 = MCD-00068: Resistor,1K5,0402,1%,1/16W; Manufacturer_Part_Number: RC0402FR-071K5L; Manufacturer: YAGEO; Provided_By: SUBCO
SB20 = MCD-00071: Solder Bridge ON; Part_Type: Mechanical; Manufacturer_Part_Number: RC0603JR-070RL; Manufacturer: YAGEO; Provided_By: SUBCO
U13 = MCD-00265: Low-Power, Stereo Codec with Headphone Amp; Part_Type: IC; Manufacturer: CIRRUS LOGIC; Provided_By: SUBCO

## Sheet Camera.SchDoc: Camera
size A4; Date: Not used; ApprovedBy: Not used; CheckedBy: Not used; Author: Not used; CompanyName: STMicroelectronics; DrawnBy: Not used; Engineer: Not used; Organization: Not used; Address1: Not used; Address2: Not used; Address3: Not used; Address4: Not used; DocumentNumber: Not used; Revision: Not used; SheetNumber: 9; SheetTotal: 17
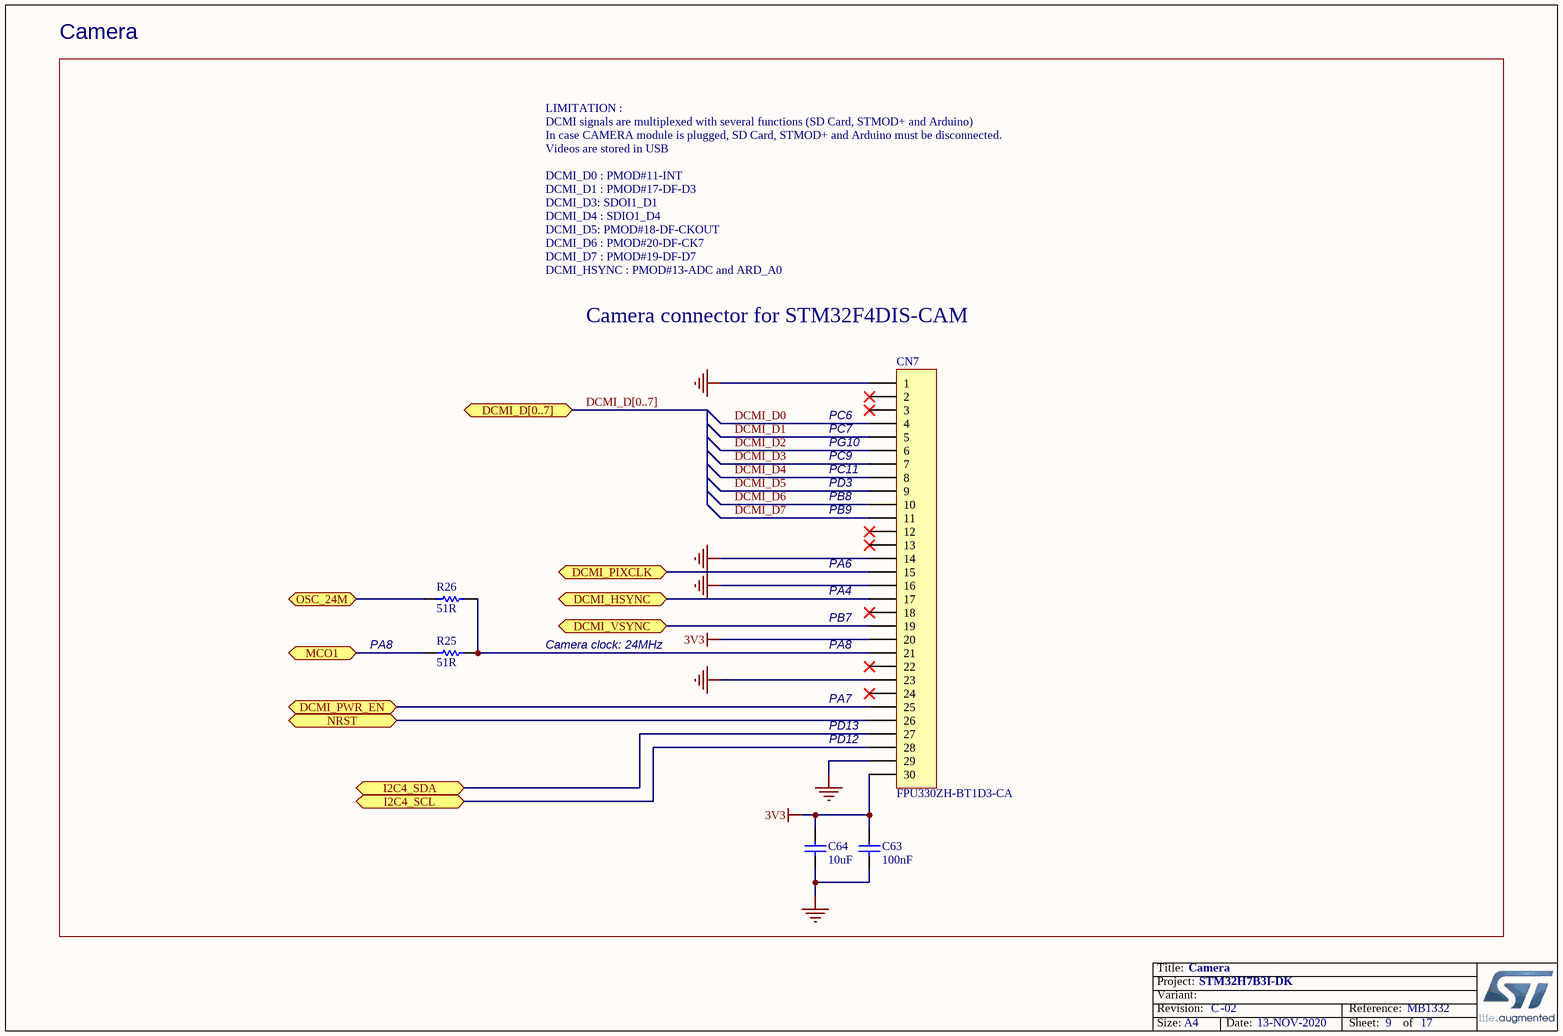
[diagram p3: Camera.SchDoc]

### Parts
C63  value 100nF  [C0402]  (hidden comment: Capacitor)
C64  value 10uF  [C0603]  (hidden comment: Capacitor)
CN7  FPU330ZH-BT1D3-CA  [CON_TOWNES_FPU330ZH-BT1D3-CA_P050]
R25  value 51R  [R0402]  (hidden comment: Resistor)
R26  value 51R  [R0402]  (hidden comment: Resistor)

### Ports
DCMI_D[0..7], DCMI_HSYNC, DCMI_PIXCLK, DCMI_PWR_EN, DCMI_VSYNC, I2C4_SCL, I2C4_SDA, MCO1, NRST, OSC_24M

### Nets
3V3: C63.2 C64.2 CN7.20 CN7.30
GND: C63.1 C64.1 CN7.1 CN7.14 CN7.16 CN7.23 CN7.29
DCMI_D0: CN7.4
DCMI_D1: CN7.5
DCMI_D2: CN7.6
DCMI_D3: CN7.7
DCMI_D4: CN7.8
DCMI_D5: CN7.9
DCMI_D6: CN7.10
DCMI_D7: CN7.11
DCMI_HSYNC: CN7.17 ; port DCMI_HSYNC
DCMI_PIXCLK: CN7.15 ; port DCMI_PIXCLK
DCMI_PWR_EN: CN7.25 ; port DCMI_PWR_EN
DCMI_VSYNC: CN7.19 ; port DCMI_VSYNC
I2C4_SCL: CN7.28 ; port I2C4_SCL
I2C4_SDA: CN7.27 ; port I2C4_SDA
MCO1: R25.1 ; port MCO1
OSC_24M: R26.1 ; port OSC_24M
T_NRST: CN7.26 ; port NRST
NetCN7_21: CN7.21 R25.2 R26.2

Not connected (* = marked no-connect by the designer): CN7 2* 3* 12* 13* 18* 22* 24*

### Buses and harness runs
bus DCMI_D[0..7] = port DCMI_D[0..7]

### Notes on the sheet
- Camera
- LIMITATION :
  DCMI signals are multiplexed with several functions (SD Card, STMOD+ and Arduino)
  In case CAMERA module is plugged, SD Card, STMOD+ and Arduino must be disconnected.
  Videos are stored in USB
  DCMI_D0 : PMOD#11-INT
  DCMI_D1 : PMOD#17-DF-D3
  DCMI_D3: SDOI1_D1
  DCMI_D4 : SDIO1_D4
  DCMI_D5: PMOD#18-DF-CKOUT
  DCMI_D6 : PMOD#20-DF-CK7
  DCMI_D7 : PMOD#19-DF-D7
  DCMI_HSYNC : PMOD#13-ADC and ARD_A0
- Camera connector for STM32F4DIS-CAM
- (near CN7) PC7
- (near CN7) PG10
- (near CN7) PC6
- (near CN7) PB8
- (near CN7) PC9
- (near CN7) PC11
- (near CN7) PD3
- (near CN7) PB9
- (near CN7) PA6
- PA8
- Camera clock: 24MHz
- (near CN7) PA4
- (near CN7) PB7
- (near CN7) PA8
- (near CN7) PA7
- (near CN7) PD12
- (near CN7) PD13

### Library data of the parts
C63 = MCD-00102: as C72 on sheet Audio_Codec
C64 = MCD-00098: as C77 on sheet Audio_Codec
CN7 = MCD-00326: Connector FFC/FPC ZIF 0.5mm 30 pins, Lower Contacts; Manufacturer: TOWNES; Provided_By: SUBCO
R25 R26 = MCD-00485: Resistor,51R,0402,1%,1/16W; Manufacturer_Part_Number: RC0402FR-0751RL; Manufacturer: YAGEO; Provided_By: SUBCO

## Sheet FDCAN.SchDoc: FDCAN
size A4; Date: Not used; ApprovedBy: Not used; CheckedBy: Not used; Author: Not used; CompanyName: STMicroelectronics; DrawnBy: Not used; Engineer: Not used; Organization: Not used; Address1: Not used; Address2: Not used; Address3: Not used; Address4: Not used; DocumentNumber: Not used; Revision: Not used; SheetNumber: 11; SheetTotal: 17
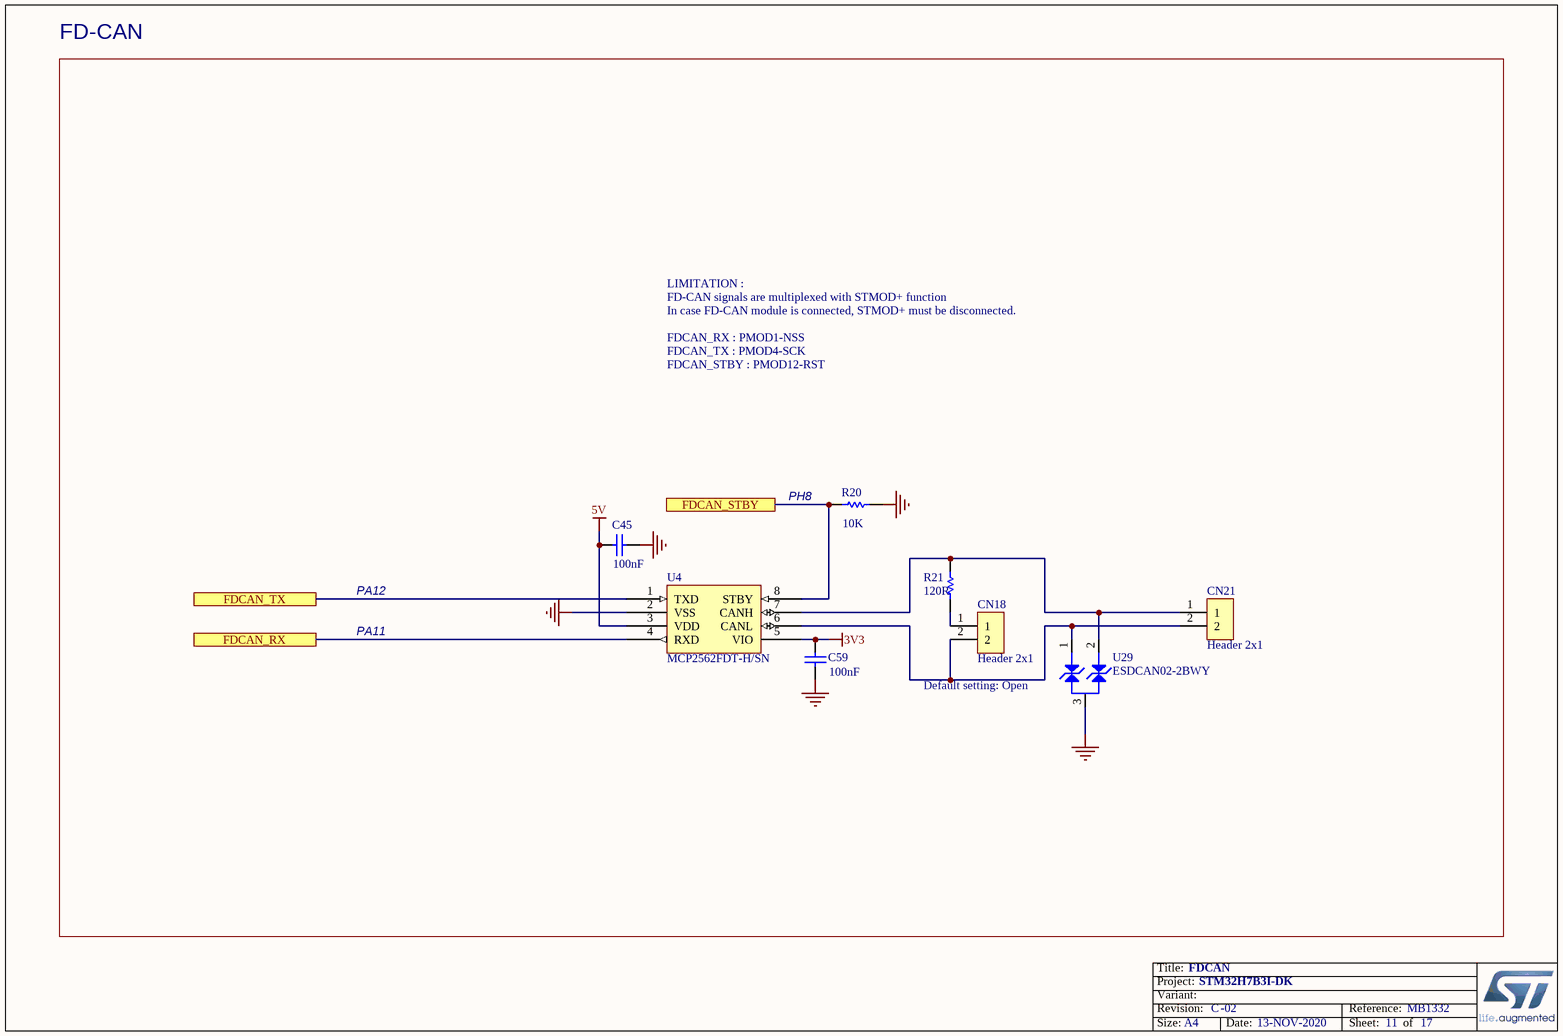
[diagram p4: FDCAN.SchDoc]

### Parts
C45  value 100nF  [C0402]  (hidden comment: Capacitor)
C59  value 100nF  [C0402]  (hidden comment: Capacitor)
CN18  Header 2x1  [CON_SAMTEC_TSW-102-07-G-S]
CN21  Header 2x1  [CON_SAMTEC_TSW-102-07-G-S]
R20  value 10K  [R0402]  (hidden comment: Resistor)
R21  value 120R  [R0402]  (hidden comment: Resistor)
U4  value MCP2562FDT-H/SN  [ICC_SO8_5X4_P127]  (hidden comment: MCP2562FD)
U29  value ESDCAN02-2BWY  [DIO_SOT323]  (hidden comment: ESD-TRANSIL-DUAL-BIDIR)

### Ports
FDCAN_RX, FDCAN_STBY, FDCAN_TX

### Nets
3V3: C59.1 U4.5(VIO)
5V: C45.1 U4.3(VDD)
GND: C45.2 C59.2 R20.2 U4.2(VSS) U29.3
FDCAN_RX: U4.4(RXD) ; port FDCAN_RX
FDCAN_STBY: R20.1 U4.8(STBY) ; port FDCAN_STBY
FDCAN_TX: U4.1(TXD) ; port FDCAN_TX
NetCN18_1: CN18.1 R21.1
NetCN18_2: CN18.2 CN21.2 U4.6(CANL) U29.1
NetCN21_1: CN21.1 R21.2 U4.7(CANH) U29.2

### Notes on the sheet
- FD-CAN
- LIMITATION :
  FD-CAN signals are multiplexed with STMOD+ function
  In case FD-CAN module is connected, STMOD+ must be disconnected.
  FDCAN_RX : PMOD1-NSS
  FDCAN_TX : PMOD4-SCK
  FDCAN_STBY : PMOD12-RST
- (near R20) PH8
- PA12
- PA11
- (near U29) Default setting: Open

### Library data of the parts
C45 C59 = MCD-00006: Capacitor, MLCC, 100nF, 16V, X7R, 10%, 0402, T=0.5mm; Manufacturer_Part_Number: CC0402KRX7R7BB104; Manufacturer: YAGEO; Alternate_Manufacturer_Part_Number: GCM155R71C104KA55D; Alternate_Manufacturer: MURATA; Provided_By: SUBCO
CN18 CN21 = MCD-00032: Header, 2x1, 2,54mm, VR, TH, Height 5.84mm/2.54mm; Part_Type: Connector; Manufacturer_Part_Number: TSW-102-07-G-S; Manufacturer: SAMTEC; Alternate_Manufacturer_Part_Number: 313102S111116; Alternate_Manufacturer: JIUBABA; Part_Preference: Recommended
R20 = MCD-00053: as R44 on sheet Audio_Codec
R21 = MCD-00194: Resistor,120R,0402,1%,1/16W; Manufacturer_Part_Number: RC0402FR-07120RL; Manufacturer: YAGEO; Provided_By: SUBCO
U4 = MCD-00129: High-Speed CAN Flexible Data Rate Transceiver; Manufacturer: MICROCHIP; Part_Type: IC; Provided_By: SUBCO
U29 = MCD-01062: Automotive dual-line Transil, transient voltage suppressor (TVS) for CAN bus. Compliant with interfaces in automotive: CAN-FD, LIN, FlexRay, MOST, SENT, USB; Part_Type: Diode; Manufacturer: STMICROELECTRONICS; BMS_Part_Number: 9179023; Provided_By: SUBCO with ST control

## Sheet LCD.SchDoc: LCD
size A4; Date: Not used; ApprovedBy: Not used; CheckedBy: Not used; Author: Not used; CompanyName: STMicroelectronics; DrawnBy: Not used; Engineer: Not used; Organization: Not used; Address1: Not used; Address2: Not used; Address3: Not used; Address4: Not used; DocumentNumber: Not used; Revision: Not used; SheetNumber: 10; SheetTotal: 17
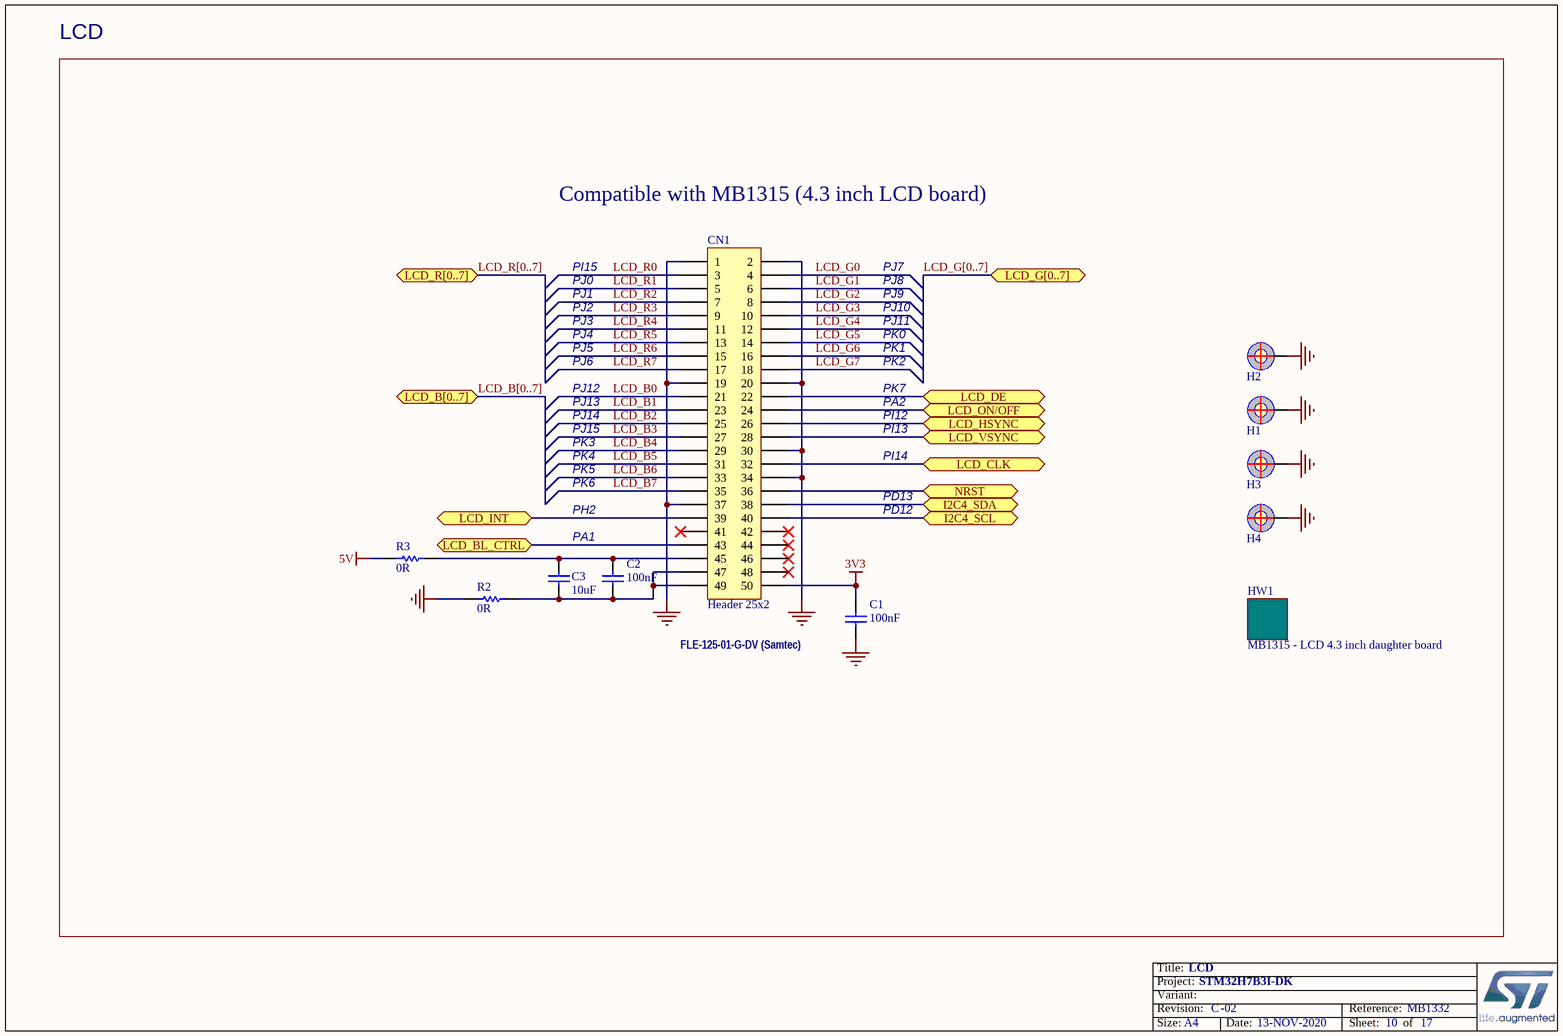
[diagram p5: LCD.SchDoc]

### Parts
C1  value 100nF  [C0402]  (hidden comment: Capacitor)
C2  value 100nF  [C0402]  (hidden comment: Capacitor)
C3  value 10uF  [C0805]  (hidden comment: Capacitor)
CN1  Header 25x2  [MOD_LCD_MB1046B__CON_SAMTEC_FLE-125-01-G-DV]
H1  POSITION HOLE  [PTH_M1261-3005-N_3P5X6_M3_H14]  (value not drawn)  (no BOM)
H2  POSITION HOLE  [PTH_M1261-3005-N_3P5X6_M3_H14]  (value not drawn)  (no BOM)
H3  POSITION HOLE  [PTH_M1261-3005-N_3P5X6_M3_H14]  (value not drawn)  (no BOM)
H4  POSITION HOLE  [PTH_M1261-3005-N_3P5X6_M3_H14]  (value not drawn)  (no BOM)
HW1  value MB1315 - LCD 4.3 inch daughter board  (hidden comment: Daughter_Board)
R2  value 0R  [R0603]  (hidden comment: Resistor)
R3  value 0R  [R0603]  (hidden comment: Resistor)

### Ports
I2C4_SCL, I2C4_SDA, LCD_B[0..7], LCD_BL_CTRL, LCD_CLK, LCD_DE, LCD_G[0..7], LCD_HSYNC, LCD_INT, LCD_ON/OFF, LCD_R[0..7], LCD_VSYNC, NRST

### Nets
3V3: C1.1 CN1.50
5V: R3.1
GND: C1.2 CN1.1 CN1.2 CN1.19 CN1.20 CN1.30 CN1.34 CN1.37 H1.1 H2.1 H3.1 H4.1 R2.1
I2C4_SCL: CN1.40 ; port I2C4_SCL
I2C4_SDA: CN1.38 ; port I2C4_SDA
LCD_B0: CN1.21
LCD_B1: CN1.23
LCD_B2: CN1.25
LCD_B3: CN1.27
LCD_B4: CN1.29
LCD_B5: CN1.31
LCD_B6: CN1.33
LCD_B7: CN1.35
LCD_BL_CTRL: CN1.43 ; port LCD_BL_CTRL
LCD_CLK: CN1.32 ; port LCD_CLK
LCD_DE: CN1.22 ; port LCD_DE
LCD_G0: CN1.4
LCD_G1: CN1.6
LCD_G2: CN1.8
LCD_G3: CN1.10
LCD_G4: CN1.12
LCD_G5: CN1.14
LCD_G6: CN1.16
LCD_G7: CN1.18
LCD_HSYNC: CN1.26 ; port LCD_HSYNC
LCD_INT: CN1.39 ; port LCD_INT
LCD_ON/OFF: CN1.24 ; port LCD_ON/OFF
LCD_R0: CN1.3
LCD_R1: CN1.5
LCD_R2: CN1.7
LCD_R3: CN1.9
LCD_R4: CN1.11
LCD_R5: CN1.13
LCD_R6: CN1.15
LCD_R7: CN1.17
LCD_VSYNC: CN1.28 ; port LCD_VSYNC
T_NRST: CN1.36 ; port NRST
NetC2_1: C2.1 C3.2 CN1.45 R3.2
NetC2_2: C2.2 C3.1 CN1.47 CN1.49 R2.2

Not connected (* = marked no-connect by the designer): CN1 41* 42* 44* 46* 48*

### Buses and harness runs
bus LCD_B[0..7] = port LCD_B[0..7]
bus LCD_G[0..7] = port LCD_G[0..7]
bus LCD_R[0..7] = port LCD_R[0..7]

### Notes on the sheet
- LCD
- Compatible with MB1315 (4.3 inch LCD board)
- PI15
- PJ0
- PJ1
- PJ2
- PJ7
- PJ8
- PJ9
- PJ10
- PJ3
- PJ4
- PJ5
- PJ6
- PJ11
- PK0
- PK1
- PK2
- PJ12
- PJ13
- PJ14
- PJ15
- PK3
- PK7
- PI12
- PI13
- PA2
- PK4
- PK5
- PK6
- PH2
- PI14
- PD12
- PD13
- PA1
- (near C1) FLE-125-01-G-DV (Samtec)

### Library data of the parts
C1 C2 = MCD-00006: as C45 on sheet FDCAN
C3 = MCD-00014: Capacitor, MLCC, 10uF, 25V, X5R, 10%, 0805, T=0,85mm; Manufacturer_Part_Number: CC0805KRX5R8BB106; Manufacturer: YAGEO; Provided_By: SUBCO
CN1 = MCD-01222: Header 25x2 for MB1046 - LCD 4.3 inches daughter board; Part_Type: Connector; Manufacturer_Part_Number: FLE-125-01-G-DV; Manufacturer: SAMTEC; Alternate_Manufacturer_Part_Number: 234250M1410; Alternate_Manufacturer: JIUBABA; Provided_By: SUBCO
H1-H4 = MCD-00035: POSITION HOLE C6D3R5; Part_Type: Mechanical
HW1 = MCD-01956: MB1315 - LCD 4.3 inch daughter board; Part_Type: Display; Manufacturer_Part_Number: MB1315 - LCD 4.3 inches daughter board; Manufacturer: STMICROELECTRONICS; Provided_By: SUBCO with ST control
R2 R3 = MCD-00056: Resistor,0R,0603,5%,1/10W; Manufacturer_Part_Number: RC0603JR-070RL; Manufacturer: YAGEO; Provided_By: SUBCO

## Sheet Memory.SchDoc: Memory
size A4; Date: Not used; ApprovedBy: Not used; CheckedBy: Not used; Author: Not used; CompanyName: STMicroelectronics; DrawnBy: Not used; Engineer: Not used; Organization: Not used; Address1: Not used; Address2: Not used; Address3: Not used; Address4: Not used; DocumentNumber: Not used; Revision: Not used; SheetNumber: 5; SheetTotal: 17
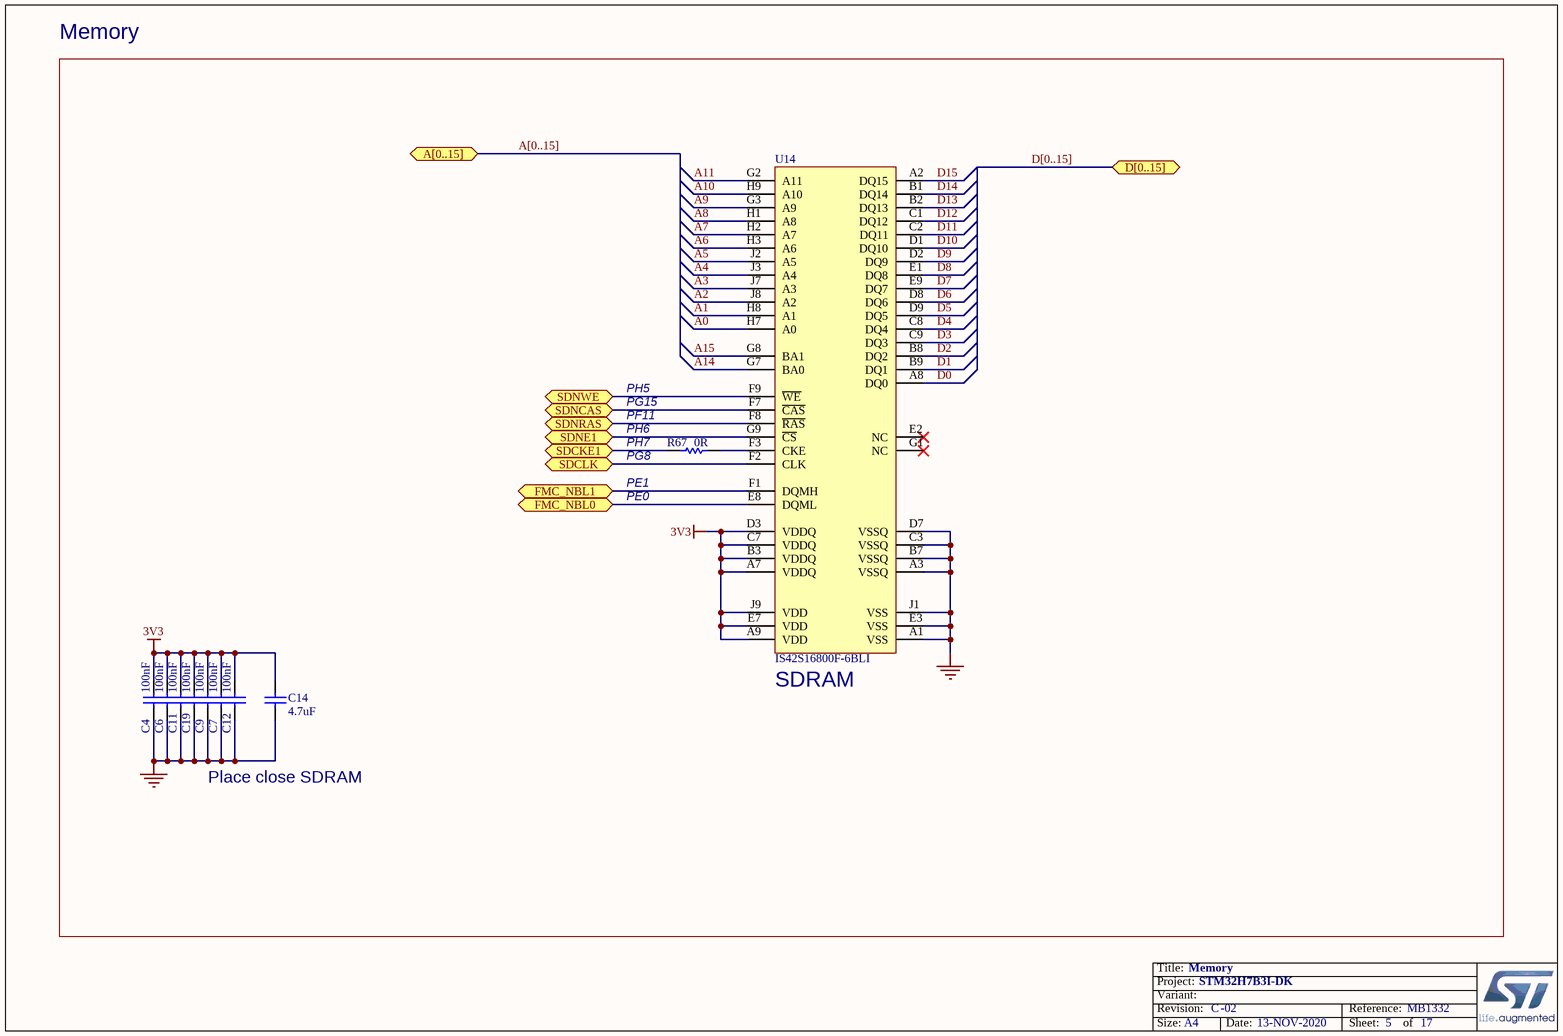
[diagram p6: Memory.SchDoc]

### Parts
C4  value 100nF  [C0402]  (hidden comment: Capacitor)
C6  value 100nF  [C0402]  (hidden comment: Capacitor)
C7  value 100nF  [C0402]  (hidden comment: Capacitor)
C9  value 100nF  [C0402]  (hidden comment: Capacitor)
C11  value 100nF  [C0402]  (hidden comment: Capacitor)
C12  value 100nF  [C0402]  (hidden comment: Capacitor)
C14  value 4.7uF  [C0603_H0P8]  (hidden comment: Capacitor)
C19  value 100nF  [C0402]  (hidden comment: Capacitor)
R67  value 0R  [R0603]  (hidden comment: Resistor)
U14  IS42S16800F-6BLI  [ICC_TFBGA54_3X9-BALL-X2_8X8_P080]

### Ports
A[0..15], D[0..15], FMC_NBL0, FMC_NBL1, SDCKE1, SDCLK, SDNCAS, SDNE1, SDNRAS, SDNWE

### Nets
3V3: C4.1 C6.1 C7.1 C9.1 C11.1 C12.1 C14.2 C19.1 U14.A7(VDDQ) U14.A9(VDD) U14.B3(VDDQ) U14.C7(VDDQ) U14.D3(VDDQ) U14.E7(VDD) U14.J9(VDD)
GND: C4.2 C6.2 C7.2 C9.2 C11.2 C12.2 C14.1 C19.2 U14.A1(VSS) U14.A3(VSSQ) U14.B7(VSSQ) U14.C3(VSSQ) U14.D7(VSSQ) U14.E3(VSS) U14.J1(VSS)
A0: U14.H7(A0)
A1: U14.H8(A1)
A2: U14.J8(A2)
A3: U14.J7(A3)
A4: U14.J3(A4)
A5: U14.J2(A5)
A6: U14.H3(A6)
A7: U14.H2(A7)
A8: U14.H1(A8)
A9: U14.G3(A9)
A10: U14.H9(A10)
A11: U14.G2(A11)
A14: U14.G7(BA0)
A15: U14.G8(BA1)
D0: U14.A8(DQ0)
D1: U14.B9(DQ1)
D2: U14.B8(DQ2)
D3: U14.C9(DQ3)
D4: U14.C8(DQ4)
D5: U14.D9(DQ5)
D6: U14.D8(DQ6)
D7: U14.E9(DQ7)
D8: U14.E1(DQ8)
D9: U14.D2(DQ9)
D10: U14.D1(DQ10)
D11: U14.C2(DQ11)
D12: U14.C1(DQ12)
D13: U14.B2(DQ13)
D14: U14.B1(DQ14)
D15: U14.A2(DQ15)
FMC_NBL0: U14.E8(DQML) ; port FMC_NBL0
FMC_NBL1: U14.F1(DQMH) ; port FMC_NBL1
SDCKE1: R67.2 ; port SDCKE1
SDCLK: U14.F2(CLK) ; port SDCLK
SDNCAS: U14.F7(~{CAS}) ; port SDNCAS
SDNE1: U14.G9(~{CS}) ; port SDNE1
SDNRAS: U14.F8(~{RAS}) ; port SDNRAS
SDNWE: U14.F9(~{WE}) ; port SDNWE
NetR67_1: R67.1 U14.F3(CKE)

Not connected (* = marked no-connect by the designer): U14 E2(NC)* G1(NC)*

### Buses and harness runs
bus A[0..15] = port A[0..15]
bus D[0..15] = port D[0..15]

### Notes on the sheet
- Memory
- PH5
- (near R67) PG15
- (near R67) PF11
- (near R67) PH6
- (near R67) PH7
- (near R67) PG8
- (near R67) PE1
- PE0
- (near U14) SDRAM
- Place close SDRAM

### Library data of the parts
C4 C6 C7 C9 C11 C12 C19 = MCD-00006: as C45 on sheet FDCAN
C14 = MCD-01721: Capacitor, 4.7uF, 10V, X5R, 10%, 0603, T=0.8mm; Manufacturer_Part_Number: CC0603KRX5R6BB475; Manufacturer: YAGEO; Provided_By: SUBCO
R67 = MCD-00056: as R2 on sheet LCD
U14 = MCD-01143: SDRAM 128Mbits - 166MHz - 54-ball BGA - x16 - 3.3V; Part_Type: IC; Manufacturer: ISSI; Provided_By: SUBCO

## Sheet OCSPI.SchDoc: OCSPI
size A4; Date: Not used; ApprovedBy: Not used; CheckedBy: Not used; Author: Not used; CompanyName: STMicroelectronics; DrawnBy: Not used; Engineer: Not used; Organization: Not used; Address1: Not used; Address2: Not used; Address3: Not used; Address4: Not used; DocumentNumber: Not used; Revision: Not used; SheetNumber: 6; SheetTotal: 17
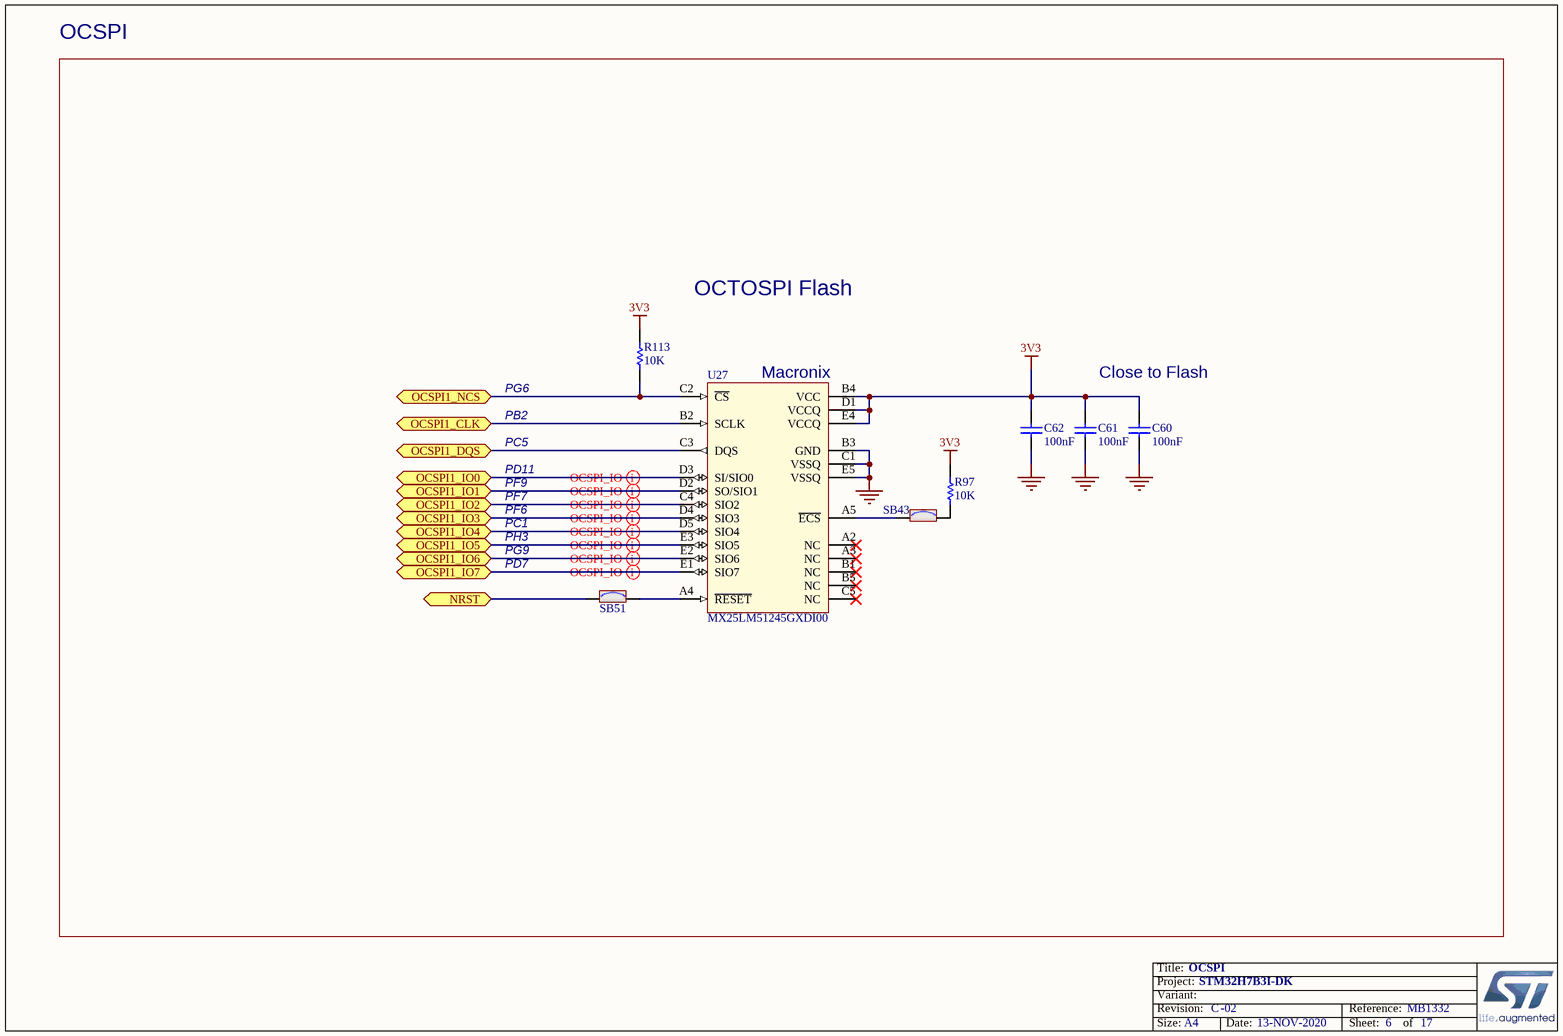
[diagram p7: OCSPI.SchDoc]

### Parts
C60  value 100nF  [C0402]  (hidden comment: Capacitor)
C61  value 100nF  [C0402]  (hidden comment: Capacitor)
C62  value 100nF  [C0402]  (hidden comment: Capacitor)
R97  value 10K  [R0402]  (hidden comment: Resistor)
R113  value 10K  [R0402]  (hidden comment: Resistor)
SB43  SB_ON  [SOLDER-BRIDGE_R0603-0R]  (value not drawn)
SB51  SB_ON  [SOLDER-BRIDGE_R0603-0R]  (value not drawn)
U27  MX25LM51245GXDI00  [ICC_BGA24_5X5-BALL-ARRAY_6X8_P1]

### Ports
NRST (bidir), OCSPI1_CLK (bidir), OCSPI1_DQS (bidir), OCSPI1_IO0 (bidir), OCSPI1_IO1 (bidir), OCSPI1_IO2 (bidir), OCSPI1_IO3 (bidir), OCSPI1_IO4 (bidir), OCSPI1_IO5 (bidir), OCSPI1_IO6 (bidir), OCSPI1_IO7 (bidir), OCSPI1_NCS (bidir)

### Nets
3V3: C60.2 C61.2 C62.2 R97.2 R113.1 U27.B4(VCC) U27.D1(VCCQ) U27.E4(VCCQ)
GND: C60.1 C61.1 C62.1 U27.B3(GND) U27.C1(VSSQ) U27.E5(VSSQ)
OCSPI1_CLK: U27.B2(SCLK) ; port OCSPI1_CLK
OCSPI1_DQS: U27.C3(DQS) ; port OCSPI1_DQS
OCSPI1_IO0: U27.D3(SI/SIO0) ; port OCSPI1_IO0
OCSPI1_IO1: U27.D2(SO/SIO1) ; port OCSPI1_IO1
OCSPI1_IO2: U27.C4(SIO2) ; port OCSPI1_IO2
OCSPI1_IO3: U27.D4(SIO3) ; port OCSPI1_IO3
OCSPI1_IO4: U27.D5(SIO4) ; port OCSPI1_IO4
OCSPI1_IO5: U27.E3(SIO5) ; port OCSPI1_IO5
OCSPI1_IO6: U27.E2(SIO6) ; port OCSPI1_IO6
OCSPI1_IO7: U27.E1(SIO7) ; port OCSPI1_IO7
OCSPI1_NCS: R113.2 U27.C2(~{CS}) ; port OCSPI1_NCS
T_NRST: SB51.1 ; port NRST
NetR97_1: R97.1 SB43.2
NetSB43_1: SB43.1 U27.A5(~{ECS})
NetSB51_2: SB51.2 U27.A4(~{RESET})

Not connected (* = marked no-connect by the designer): U27 A2(NC)* A3(NC)* B1(NC)* B5(NC)* C5(NC)*

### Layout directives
rule Undefined; rule ? ; rule ? : OCSPI1_IO0, OCSPI1_IO1, OCSPI1_IO2, OCSPI1_IO3, OCSPI1_IO4, OCSPI1_IO5, OCSPI1_IO6, OCSPI1_IO7

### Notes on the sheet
- OCSPI
- OCTOSPI Flash
- (near U27) Macronix
- Close to Flash
- PG6
- PB2
- PC5
- PD11
- PF6
- PF7
- PF9
- PH3
- PC1
- PG9
- PD7

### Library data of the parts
C60-C62 = MCD-00102: as C72 on sheet Audio_Codec
R97 R113 = MCD-00053: as R44 on sheet Audio_Codec
SB43 SB51 = MCD-00071: as SB20 on sheet Audio_Codec
U27 = MCD-00246: Memory,Octo-SPI-NOR,512Mb,2048x16,133MHz,3V,DTR,BGA24, CMOS MXSMIO; Part_Type: IC; Manufacturer: MACRONIX; ECCN_US: 3A991.b.1.a; Provided_By: SUBCO

## Sheet Peripherals.SchDoc: Peripherals
size A4; Date: Not used; ApprovedBy: Not used; CheckedBy: Not used; Author: Not used; CompanyName: STMicroelectronics; DrawnBy: Not used; Engineer: Not used; Organization: Not used; Address1: Not used; Address2: Not used; Address3: Not used; Address4: Not used; DocumentNumber: Not used; Revision: Not used; SheetNumber: 13; SheetTotal: 17
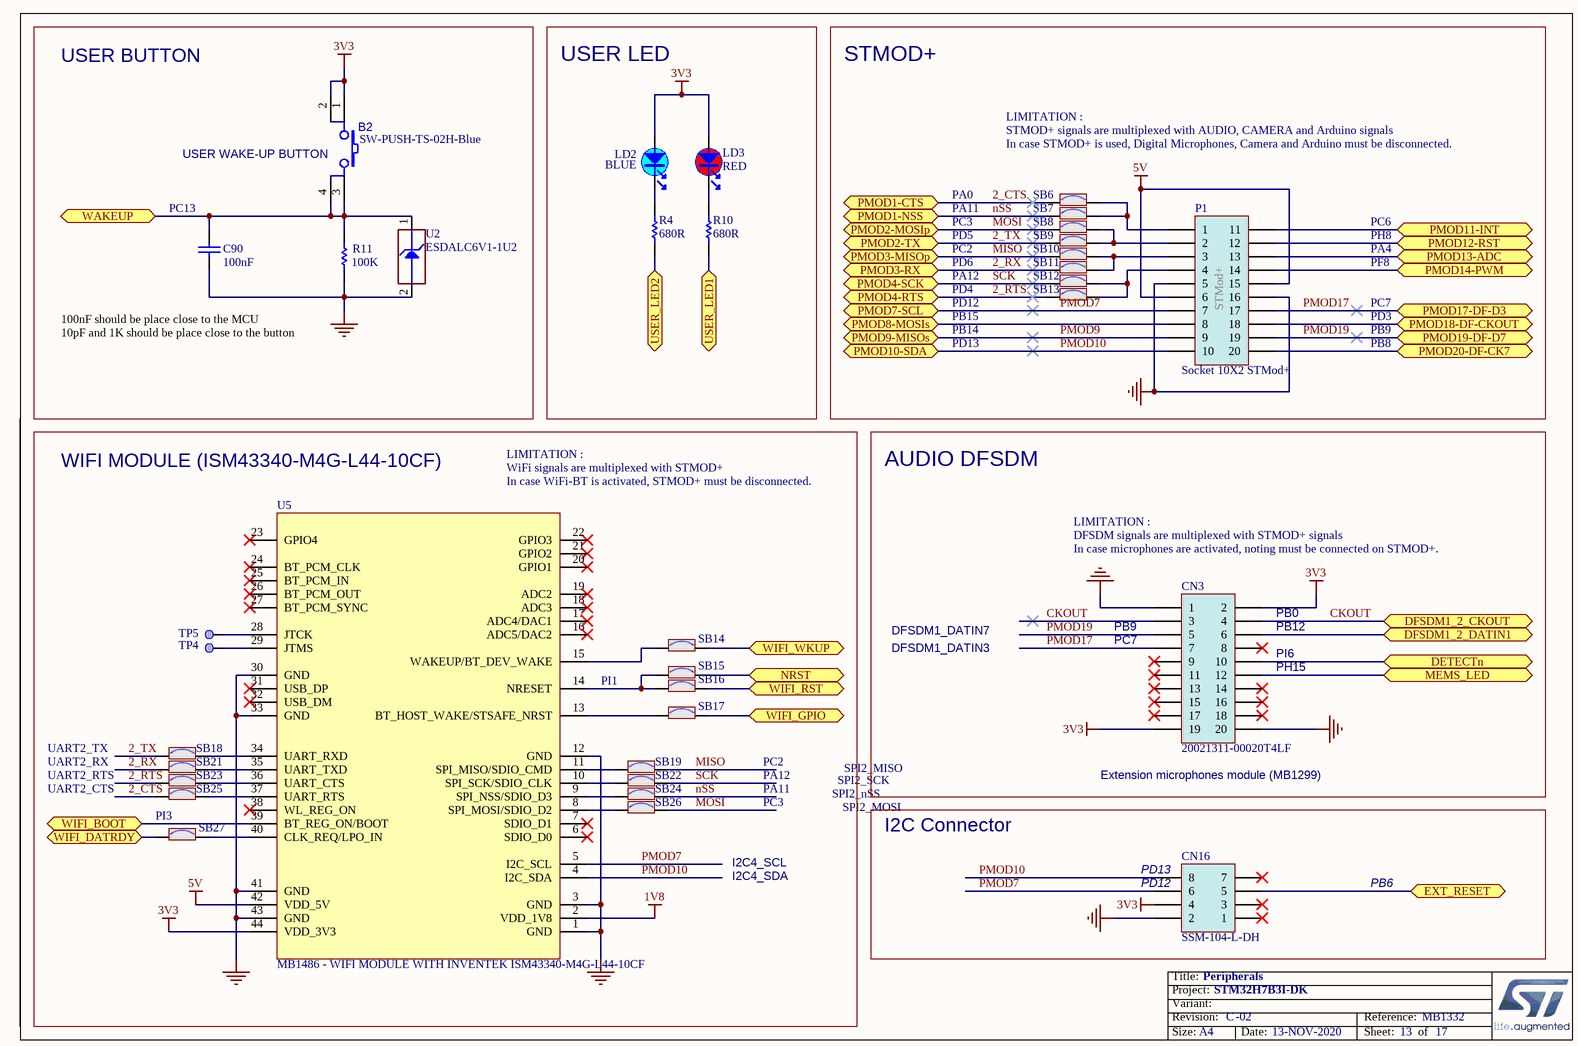
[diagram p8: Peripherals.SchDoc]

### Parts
B2  SW-PUSH-TS-02H-Blue  [SWI_JIUBABA_C-TS-02H-2-5-B-V-T_R_BLUE]
C90  value 100nF  [C0402]  (hidden comment: Capacitor)
CN3  value 20021311-00020T4LF  [CON_FCI_20021311-XXX20XXLF]  (hidden comment: Socket 10x2)
CN16  value SSM-104-L-DH  [CON_SAMTEC_SSM-104-L-DH]  (hidden comment: Socket 4x2)
LD2  value BLUE  [LED_0603_OSRAM_LB-Q39G-L2OO-35-1_BLUE_1A2K_H0P4]  (hidden comment: LED_blue)
LD3  value RED  [LED_0603_VISHAY_VLMS1300-GS08_RED_1A2K_H0P8]  (hidden comment: LED_red)
P1  Socket 10X2 STMod+  [CON_SAMTEC_SQT-110-01-F-D-RA__STMOD+]
R4  value 680R  [R0603]  (hidden comment: Resistor)
R10  value 680R  [R0603]  (hidden comment: Resistor)
R11  value 100K  [R0402]  (hidden comment: Resistor)
SB6  SB_ON  [SOLDER-BRIDGE_R0603-0R]  (value not drawn)
SB7  SB_ON  [SOLDER-BRIDGE_R0603-0R]  (value not drawn)
SB8  SB_ON  [SOLDER-BRIDGE_R0603-0R]  (value not drawn)
SB9  SB_ON  [SOLDER-BRIDGE_R0603-0R]  (value not drawn)
SB10  SB_ON  [SOLDER-BRIDGE_R0603-0R]  (value not drawn)
SB11  SB_ON  [SOLDER-BRIDGE_R0603-0R]  (value not drawn)
SB12  SB_ON  [SOLDER-BRIDGE_R0603-0R]  (value not drawn)
SB13  SB_ON  [SOLDER-BRIDGE_R0603-0R]  (value not drawn)
SB14  SB_ON  [SOLDER-BRIDGE_R0603-0R]  (value not drawn)
SB15  SB_ON  [SOLDER-BRIDGE_R0603-0R]  (value not drawn)
SB16  SB_ON  [SOLDER-BRIDGE_R0603-0R]  (value not drawn)
SB17  SB_ON  [SOLDER-BRIDGE_R0603-0R]  (value not drawn)
SB18  SB_ON  [SOLDER-BRIDGE_R0603-0R]  (value not drawn)
SB19  SB_ON  [SOLDER-BRIDGE_R0603-0R]  (value not drawn)
SB21  SB_ON  [SOLDER-BRIDGE_R0603-0R]  (value not drawn)
SB22  SB_ON  [SOLDER-BRIDGE_R0603-0R]  (value not drawn)
SB23  SB_ON  [SOLDER-BRIDGE_R0603-0R]  (value not drawn)
SB24  SB_ON  [SOLDER-BRIDGE_R0603-0R]  (value not drawn)
SB25  SB_ON  [SOLDER-BRIDGE_R0603-0R]  (value not drawn)
SB26  SB_ON  [SOLDER-BRIDGE_R0603-0R]  (value not drawn)
SB27  SB_ON  [SOLDER-BRIDGE_R0603-0R]  (value not drawn)
TP4  Test Point  [TP_SMD_0-6MM]  (value not drawn)  (no BOM)
TP5  Test Point  [TP_SMD_0-6MM]  (value not drawn)  (no BOM)
U2  value ESDALC6V1-1U2  [ESD_ST0201]  (hidden comment: ESD-TRANSIL)
U5  value MB1486 - WIFI MODULE WITH INVENTEK ISM43340-M4G-L44-10CF  [MOD_WIFI_INVENTEK_ISM43362]  (hidden comment: WIFI MODULE INTERPOSER)

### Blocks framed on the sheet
USER BUTTON: B2 C90 R11 U2
USER LED: LD2 LD3 R4 R10
STMOD+: P1 SB6-SB13
WIFI MODULE (ISM43340-M4G-L44-10CF): SB14-SB19 SB21-SB27 TP4 TP5 U5
AUDIO DFSDM: CN3
I2C Connector: CN16

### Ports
DETECTn, DFSDM1_2_CKOUT, DFSDM1_2_DATIN1, EXT_RESET, MEMS_LED, NRST, PMOD1-CTS, PMOD1-NSS, PMOD2-MOSIp, PMOD2-TX, PMOD3-MISOp, PMOD3-RX, PMOD4-RTS, PMOD4-SCK, PMOD7-SCL, PMOD8-MOSIs, PMOD9-MISOs, PMOD10-SDA, PMOD11-INT, PMOD12-RST, PMOD13-ADC, PMOD14-PWM, PMOD17-DF-D3, PMOD18-DF-CKOUT, PMOD19-DF-D7, PMOD20-DF-CK7, USER_LED1, USER_LED2, WAKEUP, WIFI_BOOT, WIFI_DATRDY, WIFI_GPIO, WIFI_RST, WIFI_WKUP

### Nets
1V8: U5.2(VDD_1V8)
3V3: B2.1 B2.2 CN3.2 CN3.19 CN16.4 LD2.1 LD3.1 U5.44(VDD_3V3)
5V: P1.6 P1.15 U5.42(VDD_5V)
GND: C90.1 CN3.1 CN3.20 CN16.2 P1.5 P1.16 R11.1 U2.2(GND) U5.1(GND) U5.3(GND) U5.12(GND) U5.30(GND) U5.33(GND) U5.41(GND) U5.43(GND)
2_CTS: SB6.1 SB25.2 ; port PMOD1-CTS
2_RTS: SB13.1 SB23.2 ; port PMOD4-RTS
2_RX: SB11.1 SB21.2 ; port PMOD3-RX
2_TX: SB9.1 SB18.2 ; port PMOD2-TX
CKOUT: CN3.3 CN3.4 ; port DFSDM1_2_CKOUT
DCMI_D0: P1.11 ; port PMOD11-INT
DCMI_D5: P1.18 ; port PMOD18-DF-CKOUT
DCMI_D6: P1.20 ; port PMOD20-DF-CK7
DETECTn: CN3.10 ; port DETECTn
DFSDM1_2_DATIN1: CN3.6 ; port DFSDM1_2_DATIN1
EXT_RESET: CN16.5 ; port EXT_RESET
MEMS_LED: CN3.12 ; port MEMS_LED
MISO: SB10.1 SB19.1 ; port PMOD3-MISOp
MOSI: SB8.1 SB26.1 ; port PMOD2-MOSIp
nSS: SB7.1 SB24.1 ; port PMOD1-NSS
PH8: P1.12 ; port PMOD12-RST
PMOD7: CN16.6 P1.7 U5.5(I2C_SCL) ; port PMOD7-SCL
PMOD8-MOSIs: P1.8 ; port PMOD8-MOSIs
PMOD9: P1.9 ; port PMOD9-MISOs
PMOD10: CN16.8 P1.10 U5.4(I2C_SDA) ; port PMOD10-SDA
PMOD13-ADC: P1.13 ; port PMOD13-ADC
PMOD14-PWM: P1.14 ; port PMOD14-PWM
PMOD17: CN3.7 P1.17 ; port PMOD17-DF-D3  [project net DCMI_D1]
PMOD19: CN3.5 P1.19 ; port PMOD19-DF-D7  [project net DCMI_D7]
SCK: SB12.1 SB22.1 ; port PMOD4-SCK  [project net PA12]
T_NRST: SB15.2 ; port NRST
USER_LED1: R10.2 ; port USER_LED1
USER_LED2: R4.2 ; port USER_LED2
WAKEUP: B2.3 B2.4 C90.2 R11.2 U2.1(IO1) ; port WAKEUP
WIFI_BOOT: U5.39(BT_REG_ON/BOOT) ; port WIFI_BOOT
WIFI_DATRDY: SB27.1 ; port WIFI_DATRDY
WIFI_GPIO: SB17.2 ; port WIFI_GPIO
WIFI_RST: SB16.2 ; port WIFI_RST
WIFI_WKUP: SB14.2 ; port WIFI_WKUP
NetLD2_2: LD2.2 R4.1
NetLD3_2: LD3.2 R10.1
NetP1_1: P1.1 SB6.2 SB7.2
NetP1_2: P1.2 SB8.2 SB9.2
NetP1_3: P1.3 SB10.2 SB11.2
NetP1_4: P1.4 SB12.2 SB13.2
NetSB14_1: SB14.1 U5.15(WAKEUP/BT_DEV_WAKE)
NetSB15_1: SB15.1 SB16.1 U5.14(NRESET)
NetSB17_1: SB17.1 U5.13(BT_HOST_WAKE/STSAFE_NRST)
NetSB18_1: SB18.1 U5.34(UART_RXD)
NetSB19_2: SB19.2 U5.11(SPI_MISO/SDIO_CMD)
NetSB21_1: SB21.1 U5.35(UART_TXD)
NetSB22_2: SB22.2 U5.10(SPI_SCK/SDIO_CLK)
NetSB23_1: SB23.1 U5.36(UART_CTS)
NetSB24_2: SB24.2 U5.9(SPI_NSS/SDIO_D3)
NetSB25_1: SB25.1 U5.37(UART_RTS)
NetSB26_2: SB26.2 U5.8(SPI_MOSI/SDIO_D2)
NetSB27_2: SB27.2 U5.40(CLK_REQ/LPO_IN)
NetTP4_1: TP4.1 U5.29(JTMS)
NetTP5_1: TP5.1 U5.28(JTCK)

Not connected (* = marked no-connect by the designer): CN3 8* 9* 11* 13* 14* 15* 16* 17* 18*; CN16 1* 3* 7*; U5 6(SDIO_D0)* 7(SDIO_D1)* 16(ADC5/DAC2)* 17(ADC4/DAC1)* 18(ADC3)* 19(ADC2)* 20(GPIO1)* 21(GPIO2)* 22(GPIO3)* 23(GPIO4)* 24(BT_PCM_CLK)* 25(BT_PCM_IN)* 26(BT_PCM_OUT)* 27(BT_PCM_SYNC)* 31(USB_DP)* 32(USB_DM)* 38(WL_REG_ON)*

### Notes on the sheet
- (near B2) USER WAKE-UP BUTTON
- LIMITATION :
  STMOD+ signals are multiplexed with AUDIO, CAMERA and Arduino signals
  In case STMOD+ is used, Digital Microphones, Camera and Arduino must be disconnected.
- (near C90) PC13
- PA0
- PC3
- PD5
- PC2
- PA11
- PC6
- PH8
- PA4
- PD6
- PA12
- PD12
- PB15
- PD4
- PF8
- PC7
- PD3
- 100nF should be place close to the MCU
  10pF and 1K should be place close to the button
- PD13
- PB14
- PB9
- PB8
- LIMITATION :
  WiFi signals are multiplexed with STMOD+
  In case WiFi-BT is activated, STMOD+ must be disconnected.
- DFSDM1_DATIN3
- DFSDM1_DATIN7
- (near CN3) LIMITATION :
  DFSDM signals are multiplexed with STMOD+ signals
  In case microphones are activated, noting must be connected on STMOD+.
- (near CN3) PB9
- (near CN3) PC7
- (near CN3) PB0
- (near CN3) PB12
- (near CN3) PI6
- PI1
- (near CN3) PH15
- UART2_TX
- UART2_RX
- UART2_RTS
- UART2_CTS
- SPI2_nSS
- SPI2_SCK
- SPI2_MISO
- (near CN3) Extension microphones module (MB1299)
- PI3
- SPI2_MOSI
- I2C4_SCL
- I2C4_SDA
- (near CN16) PD13
- (near CN16) PD12
- PB6

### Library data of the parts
B2 = MCD-00172: Switch HW SMD blue; Part_Type: Misc; Manufacturer_Part_Number: C-TS-02H-2.5-B-V-T/R BLUE; Manufacturer: JIUBABA; Provided_By: SUBCO
C90 = MCD-00006: as C45 on sheet FDCAN
CN3 = MCD-00147: Socket for MB1299, 10x2, 1.27mm, VR, TH, Height 4.30mm/2.40mm; Part_Type: Connector; Manufacturer: FCI; Alternate_Manufacturer_Part_Number: 234220S1410; Alternate_Manufacturer: JIUBABA; Provided_By: SUBCO
CN16 = MCD-00131: Socket, 4x2, 2.54mm, RA, SMT, Height 5.72mm; Manufacturer: SAMTEC; Part_Type: Connector; Alternate_Manufacturer_Part_Number: F206A-2x04MGF-LA; Alternate_Manufacturer: JIUBABA; Provided_By: SUBCO
LD2 = MCD-00585: LED Blue, 0603 SMD, Forward Voltage Min=2,8V, Max=3,8V; Manufacturer_Part_Number: LB Q39G-L2OO-35-1; Manufacturer: OSRAM OPTO SEMICONDUCTORS; Part_Type: Display; Alternate_Manufacturer_Part_Number: 19-217-BHC-ZL1M2RY-3T-V4; Alternate_Manufacturer: EVERLIGHT; Order_Code_RS: 9148643; Provided_By: SUBCO
LD3 = MCD-00587: LED Red, 0603 SMD, 2V Forward Voltage; Manufacturer_Part_Number: VLMS1300-GS08; Manufacturer: VISHAY; Alternate_Manufacturer_Part_Number: LS Q976-NR-1; Alternate_Manufacturer: OSRAM OPTO SEMICONDUCTORS; Part_Type: Display; Provided_By: SUBCO
P1 = MCD-00309: Socket 10x2, 2.00mm, RA, TH, Height 6.35mm/2.29mm; Part_Type: Connector; Manufacturer_Part_Number: SQT-110-01-F-D-RA; Manufacturer: SAMTEC; Alternate_Manufacturer_Part_Number: FH200020C-12300; Alternate_Manufacturer: JIUBABA; Provided_By: SUBCO
R4 R10 = MCD-00508: Resistor,680R,0603,1%,1/10W; Manufacturer_Part_Number: RC0603FR-07680RL; Manufacturer: YAGEO; Provided_By: SUBCO
R11 = MCD-00059: as R34 on sheet Audio_Codec
SB6-SB19 SB21-SB27 = MCD-00071: as SB20 on sheet Audio_Codec
TP4 TP5 = MCD-00631: Test Point 0.6mm; Part_Type: Mechanical
U2 = MCD-00170: ESD protection 6V1; Part_Type: Diode; Manufacturer: STMICROELECTRONICS; BMS_Part_Number: 9151132; Provided_By: SUBCO with ST control
U5 = MCD-01999: 44 pins Interposer for WIFI module (MB1486 module is with INVENTEK ISM43340-M4G-L44-10CF); Part_Type: Misc; Manufacturer: STMICROELECTRONICS; ECCN_US: 5A992C; Provided_By: SUBCO with ST control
